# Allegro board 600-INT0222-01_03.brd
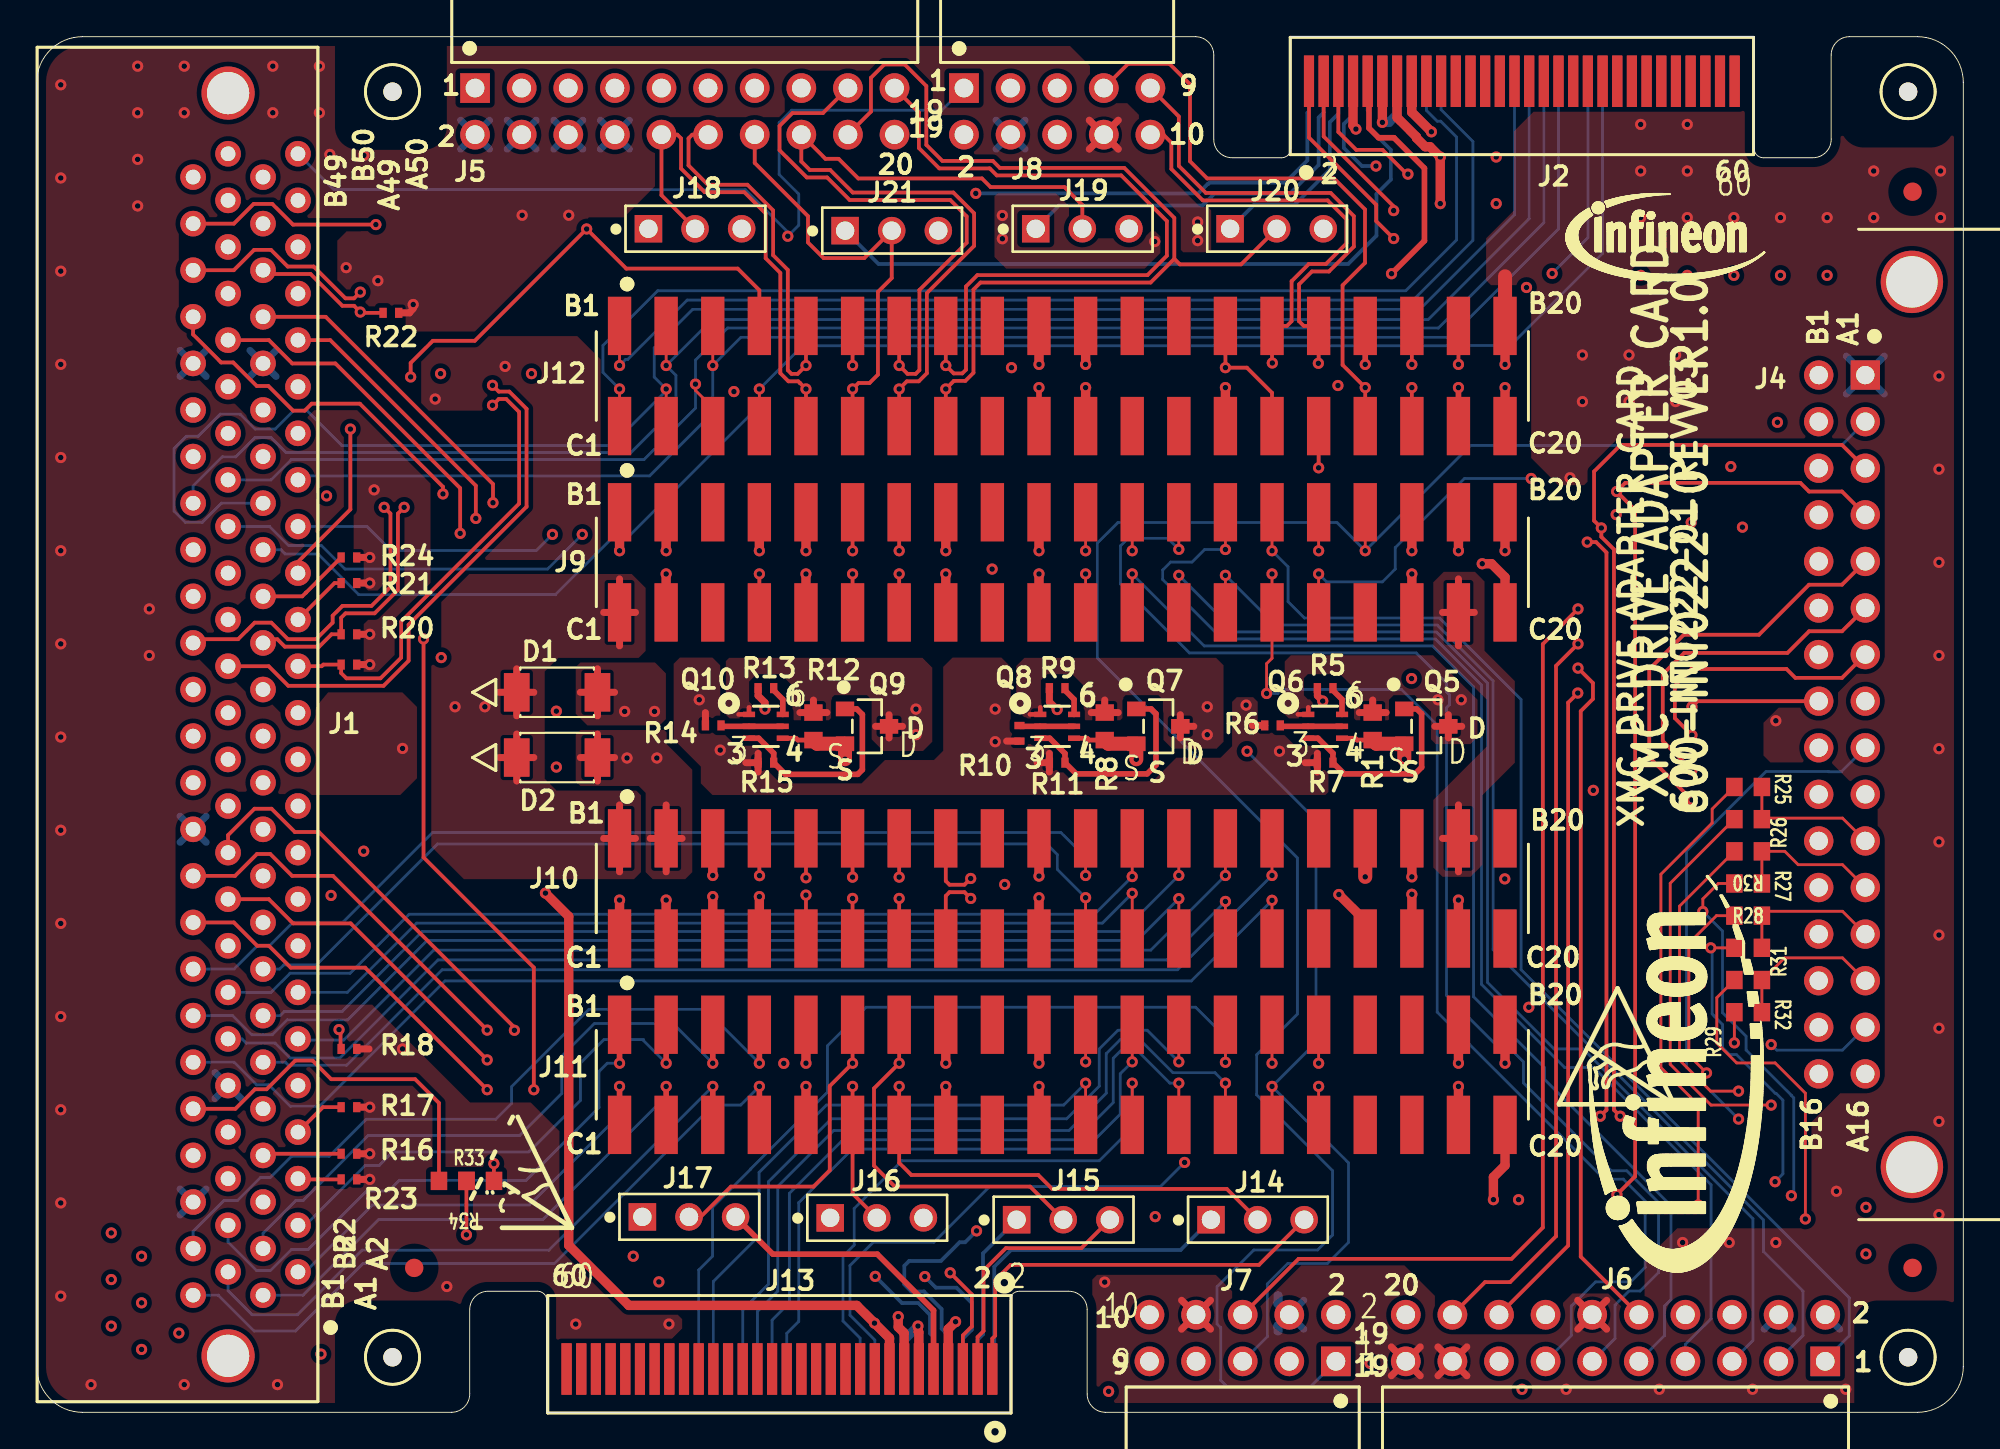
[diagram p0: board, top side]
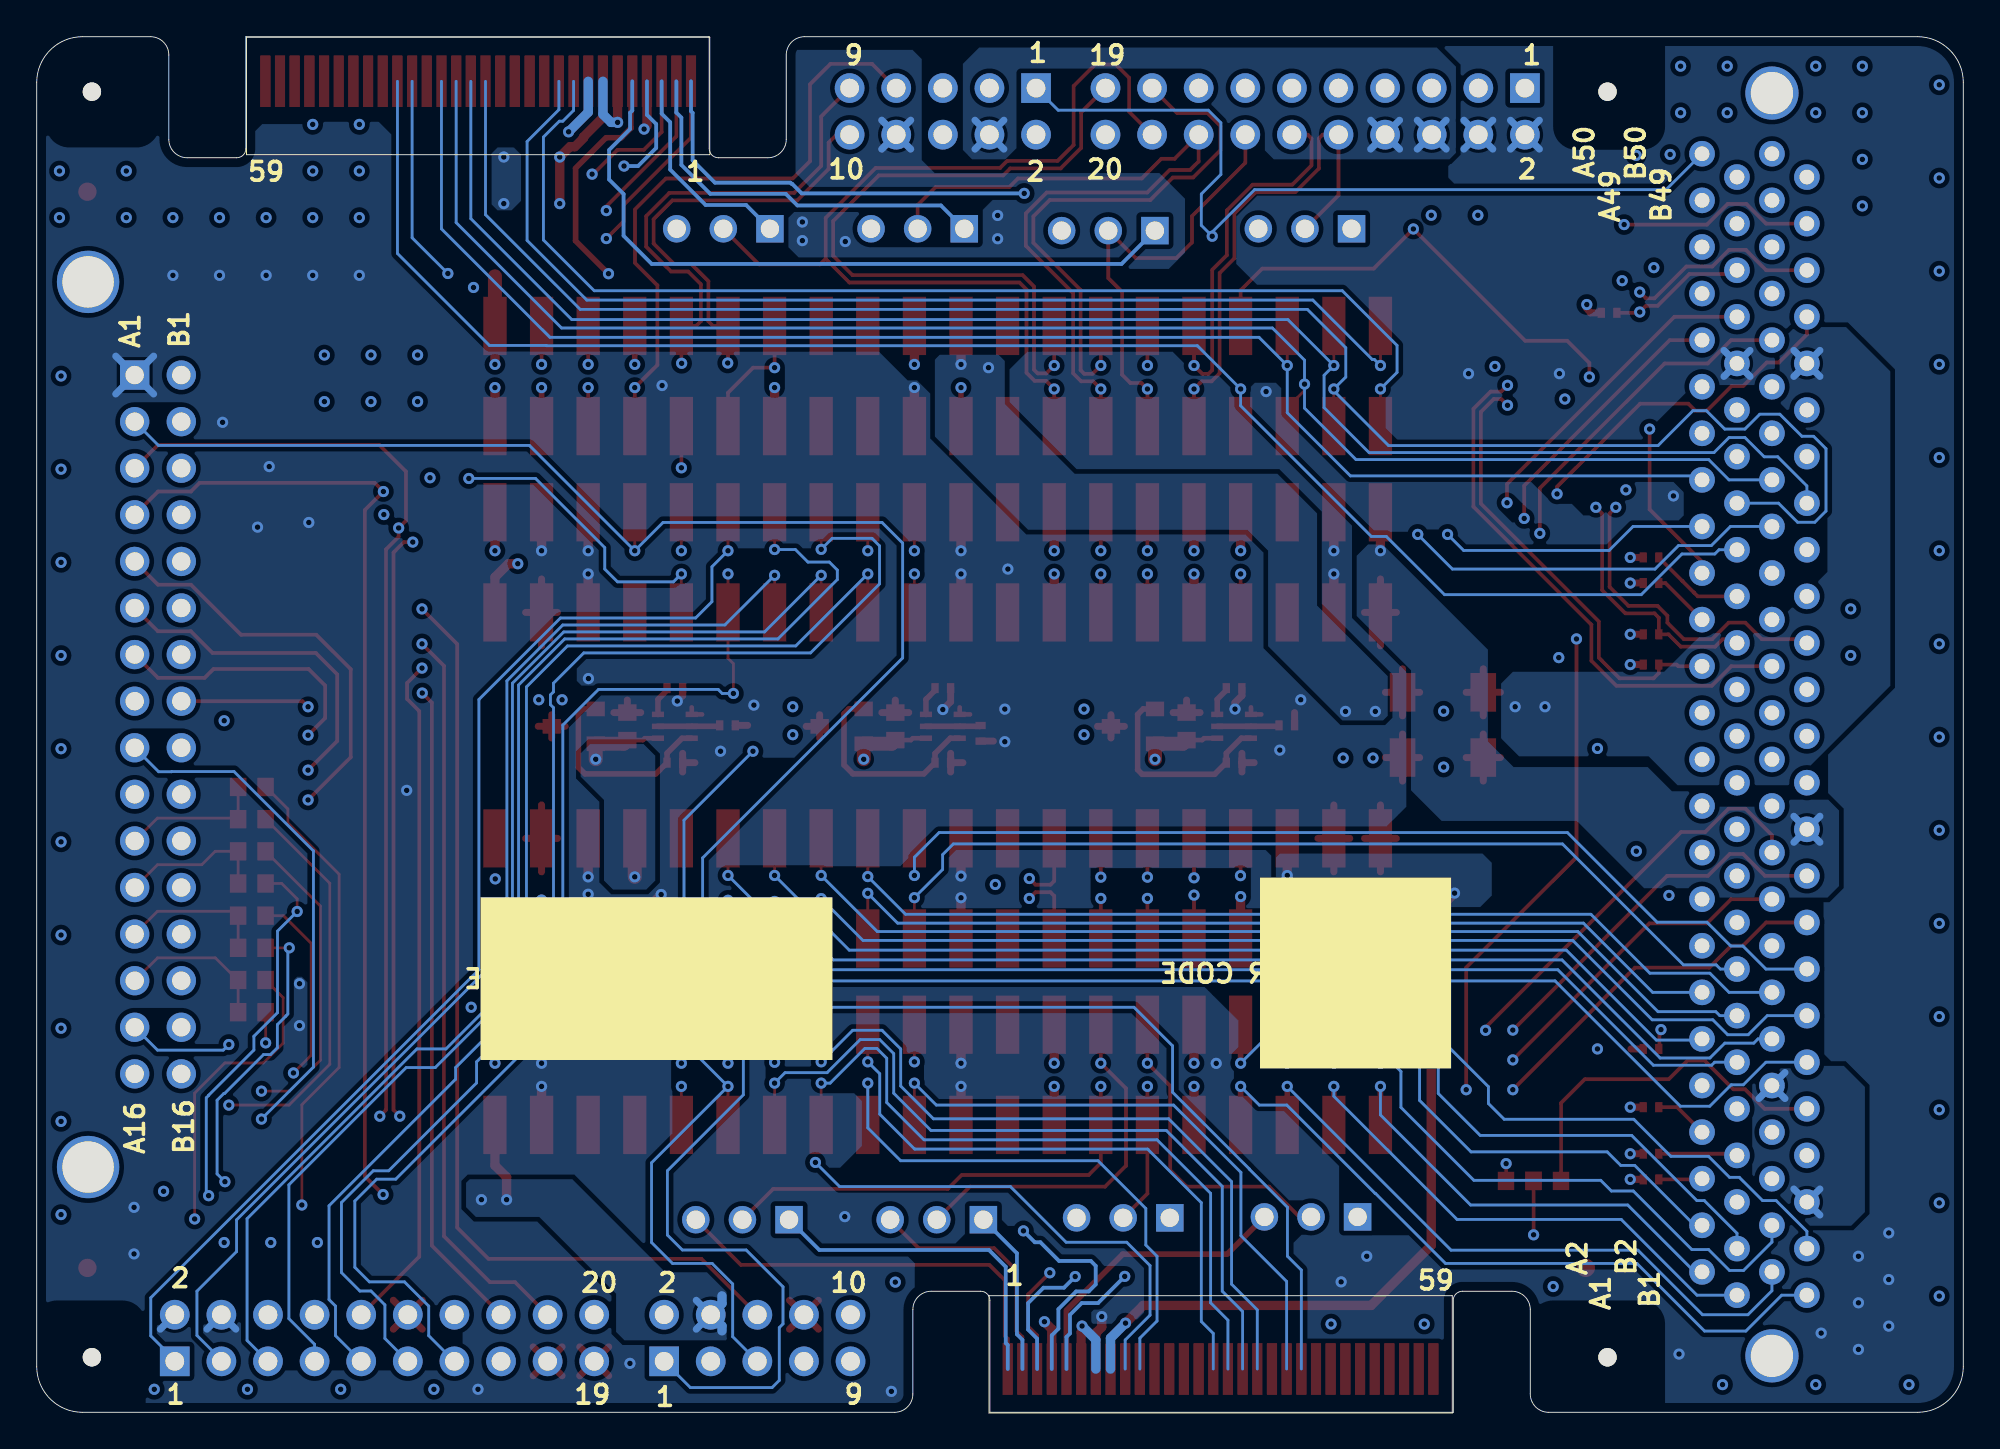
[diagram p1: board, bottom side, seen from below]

Outline 105 x 75 mm; copper layers: TOP, L02_AGND, L03_SIG1, LO4_SIG2, L05_DGND, BOTTOM. Coordinates in mm from the lower left corner of the outline.
Outline path: 0,72.5 0,2.5 arc(0.73,0.73) 2.5,0 22.6,0 arc(23.31,0.29) 23.6,1 23.6,5.6 arc(23.89,6.31) 24.6,6.6 27.3,6.6 arc(27.65,6.45) 27.8,6.1 27.8,0 53.05,0 53.05,6.1 arc(53.2,6.45) 53.55,6.6 56.25,6.6 arc(56.96,6.31) 57.25,5.6 57.25,1 arc(57.54,0.29) 58.25,0 102.5,0 arc(104.27,0.73) 105,2.5 105,72.5 arc(104.27,74.27) 102.5,75 98.8,75 arc(98.09,74.71) 97.8,74 97.8,69.4 arc(97.51,68.69) 96.8,68.4 94.1,68.4 arc(93.75,68.55) 93.6,68.9 93.6,75 68.35,75 68.35,68.9 arc(68.2,68.55) 67.85,68.4 65.15,68.4 arc(64.44,68.69) 64.15,69.4 64.15,74 arc(63.86,74.71) 63.15,75 2.5,75 arc(0.73,74.27) 0,72.5

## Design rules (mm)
constraint set DEFAULT: min track width 0.305
net group DP8_2: nets P8_2_VBEMF_U/IU(3)/PFC_I_PHASE_IN_A P8_2_VBEMF_U/IU(3)/PFC_I_PHASE_IN_A_N
net group DP9_1: nets P9_1_PFC_V_PHASE_IN_A P9_1_PFC_V_PHASE_IN_A_N
net group DP10_7: nets P10_7_VBEMF_V/IV(3)/PFC_I_PHASE_IN_B P10_7_VBEMF_V/IV(3)/PFC_I_PHASE_IN_B_N
net group DP11_0: nets P11_0_VBEMF_U/IU(1) P11_0_VBEMF_U/IU(1)_N
net group DP11_1: nets P11_1_VBEMF_V/IV(1) P11_1_VBEMF_V/IV(1)_N
net group DP11_2: nets P11_2_VBEMF_W/IW(1) P11_2_VBEMF_W/IW(1)_N
net group DP17_5: nets P17_5_VBEMF_W/IW(3)/PFC_I_PHASE_IN_C P17_5_VBEMF_W/IW(3)/PFC_I_PHASE_IN_C_N
net group DP17_6: nets P17_6_IAVG_IDCLINK(3) P17_6_IAVG_IDCLINK(3)_N
net group ANALOG_SIGNALS: nets P8_1_VBEMF_U/IU(2) P8_1_VBEMF_U/IU(2)_L P8_1_VBEMF_U/IU(2)_R P8_2_VBEMF_U/IU(3)/PFC_I_PHASE_IN_A_L P8_2_VBEMF_U/IU(3)/PFC_I_PHASE_IN_A_R P8_3_IAVG_IDCLINK(2)_L P8_4_VDCLINK1 P9_0_VBEMF_U/IU(4) P10_4_VBEMF_V/IV(4) P10_6_VBEMF_V/IV(2) P10_6_VBEMF_V/IV(2)_L P10_6_VBEMF_V/IV(2)_R P10_7_VBEMF_V/IV(3)/PFC_I_PHASE_IN_B_L P10_7_VBEMF_V/IV(3)/PFC_I_PHASE_IN_B_R P12_0_PFC_V_PHASE_IN_B P12_5_PFC_OVERCURRENT_PROT P12_6_PFC_NTC P16_3_ADC_BOARDIDENT/EXTRA_ADC4 P17_0_PFC_V_PHASE_IN_C P17_3_VBEMF_W/IW(4) P17_4_VBEMF_W/IW(2) P17_4_VBEMF_W/IW(2)_L P17_4_VBEMF_W/IW(2)_R P17_5_VBEMF_W/IW(3)/PFC_I_PHASE_IN_C_L P17_5_VBEMF_W/IW(3)/PFC_I_PHASE_IN_C_R P17_6_IAVG_IDCLINK(3)_L P17_7_IDCLINK(4) P19_0_PFC_V_DC_OUT_1 P19_1_PFC_V_DC_OUT_2 P20_0_EXTRA _ADC1/DC_LINK2 P20_1_EXTRA_ADC2/DC_LINK3 P20_2_EXTRA_ADC3
net group DIGITAL_SIGNALS: nets P1_2_CTRAP_1 P1_3_CTRAP_2 P2_4_CTRAP_3 P4_4_ENPOW1 P8_0_ENPOW2 P9_2_BRAKEGATE1 P9_3_BRAKETEMP1 P10_0_PFC_KIL_EXTRA1 P10_1_EXTRA2 P10_2_EXTRA3 P10_3_EXTRA4 P18_0_PFC_RELAY1 P18_1_PFC_RELAY2 P18_2_ENPOW3 P18_3_ENPOW4 P18_6_PWM_SYNCHRO_RECT_HIGH P18_7_PWM_SYNCHRO_RECT_LOW P23_3_CTRAP4
net group DP10_5: nets P10_5_IAVG/IDCLINK(1)_N
net group M5CONN_J4_A8PIN: nets M5CONN_J4_A8PIN P8_3_IAVG_IDCLINK(2) P10_5_IAVG/IDCLINK(1)
net group P3_0_SCB6_MISO: nets P3_0_SCB6_MISO P7_2_V2_H P7_2_V2_H/MISO
net group P3_1_SCB6_MOSI: nets P3_1_SCB6_MOSI P7_3_V2_L P7_3_V2_L/MOSI
net group P3_2_SCB6_CLK: nets P3_2_SCB6_CLK P7_4_W2_H P7_4_W2_H/CLK
net group P3_3_SCB6_SEL0: nets P3_3_SCB6_SEL0 P7_5_W2_L P7_5_W2_L/SEL0
net group SPI_HS: nets P2_1_SCB7_SDA P2_2_SCB7_SCL P3_4_SCB6_SEL1 P3_5_SCB6_SEL2

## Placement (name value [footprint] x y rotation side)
D1  PMEG3030EP,115  [DIO_NXP_SOD-128]  28.36 39.25 0 top
D2  PMEG3030EP,115  [DIO_NXP_SOD-128]  28.36 35.7 0 top
J1  FX2-100P-1.27DS(71)  [HIROSE_FX2-100P-1P27DS-71]  14.24 7.66 270 top
J2  HSEC8-130-01-L-RA_Edge_finger  [SAMTEC_HSEC8_130_EDGE]  80.94 71.77 0 top
J4  9221322921  [HARTING_9221322921]  99.66 56.55 90 top
J5  PH2RA-20-UA  [ADAMTECH_PH2RA-20-UA_CUST]  46.75 72.2 180 top
J6  PH2RA-20-UA  [ADAMTECH_PH2RA-20-UA_CUST]  74.62 2.78 0 top
J7  PH2RA-10-UA  [ADAMTECH_PH2RA-10-UA_CUST]  60.65 2.78 0 top
J8  PH2RA-10-UA  [ADAMTECH_PH2RA-10-UA_CUST]  60.7 72.2 180 top
J9  95157-440LF  [AMPHENOL_95157-440LF]  55.9 46.34 0 top
J10  95157-440LF  [AMPHENOL_95157-440LF]  55.9 28.56 0 top
J11  95157-440LF  [AMPHENOL_95157-440LF]  55.9 18.4 0 top
J12  95157-440LF  [AMPHENOL_95157-440LF]  55.9 56.5 0 top
J13  HSEC8-130-01-L-RA_Edge_finger  [SAMTEC_HSEC8_130_EDGE]  40.48 3.16 180 top
J14  HDR 3  [CTST254P1X03_W260]  64 10.5 0 top
J15  HDR 3  [CTST254P1X03_W260]  53.41 10.5 0 top
J16  HDR 3  [CTST254P1X03_W260]  43.25 10.6 0 top
J17  HDR 3  [CTST254P1X03_W260]  33.01 10.65 0 top
J18  HDR 3  [CTST254P1X03_W260]  33.34 64.53 0 top
J19  HDR 3  [CTST254P1X03_W260]  54.45 64.53 0 top
J20  HDR 3  [CTST254P1X03_W260]  65.04 64.53 0 top
J21  HDR 3  [CTST254P1X03_W260]  44.06 64.43 0 top
NOREF  -  []  50.54 69.66 0 top
NOREF#2  -  [unnamed#2]  101.99 3 0 top
NOREF#3  -  []  30.5 30.98 0 top
NOREF#4  -  []  34.31 21.13 0 top
NOREF#5  -  []  48.02 70.1 0 top
NOREF#6  -  []  68.31 74.97 0 top
NOREF#7  -  []  81.3 54.09 90 top
NOREF#8  -  [unnamed#2]  20.57 7.87 0 top
NOREF#9  -  []  30.5 58.92 0 top
NOREF#10  -  []  98.75 -1.12 90 top
NOREF#11  -  []  23.6 1 0 top
NOREF#12  -  []  73.35 -7.12 90 top
NOREF#13  -  []  68.35 74.45 0 top
NOREF#14  -  []  14.24 12.74 90 top
NOREF#15  -  []  0.02 0.58 0 top
NOREF#16  -  []  12.33 67.35 90 top
NOREF#17  -  []  27.65 6.46 0 top
NOREF#18  -  []  124.05 26.95 0 top
NOREF#19  -  []  81.3 15.99 90 top
NOREF#20  -  []  61.97 70.1 90 top
NOREF#21  -  []  34.31 49.07 0 top
NOREF#22  -  []  0 71.71 0 top
NOREF#23  -  []  23.89 69.66 90 top
NOREF#24  -  [unnamed#2]  19.39 3 0 top
NOREF#25  -  []  36.59 69.66 0 top
NOREF#26  -  []  53.05 0 0 top
NOREF#27  -  []  12.33 8.93 0 top
NOREF#28  -  []  27.85 -0.04 0 top
NOREF#29  -  []  57.25 1 0 top
NOREF#30  -  []  0 2.5 0 top
NOREF#31  -  []  186.99 280.67 0 top
NOREF#32  -  []  48.02 71.1 90 top
NOREF#33  -  []  0 2.5 0 top
NOREF#34  -  []  27.8 0 0 top
NOREF#35  -  []  34.31 59.23 0 top
NOREF#36  -  []  10.43 3.08 90 top
NOREF#37  -  []  59.38 -1.12 90 top
NOREF#38  -  []  34.31 31.29 0 top
NOREF#39  -  []  102.2 13.37 90 top
NOREF#40  -  []  127 44.55 0 top
NOREF#41  -  []  12.33 67.35 90 top
NOREF#42  -  []  13.79 -44.65 0 top
NOREF#43  -  []  24.03 6.42 0 top
NOREF#44  -  []  59.38 -7.12 90 top
NOREF#45  -  []  61.97 70.1 0 top
NOREF#46  -  []  81.3 26.15 90 top
NOREF#47  -  []  99.3 64.5 90 top
NOREF#48  -  []  93.6 74.08 0 top
NOREF#49  -  []  0.64 74.17 0 top
NOREF#50  -  []  8.52 67.35 90 top
NOREF#51  -  []  8.52 6.39 0 top
NOREF#52  -  []  73.35 -1.12 90 top
NOREF#53  -  []  93.6 73.33 0 top
NOREF#54  -  []  97.12 38.77 90 top
NOREF#55  -  []  15.32 0.58 90 top
NOREF#56  -  []  4.52 0 90 top
NOREF#57  -  []  27.85 -0.04 90 top
NOREF#58  -  []  93.56 68.57 90 top
NOREF#59  -  []  128.95 69.84 0 top
NOREF#60  -  []  59.38 -7.12 0 top
NOREF#61  -  []  30.5 20.82 0 top
NOREF#62  -  []  31.77 53.77 90 top
NOREF#63  -  []  31.77 43.61 90 top
NOREF#64  -  []  102.2 13.37 90 top
NOREF#65  -  []  68.27 5.32 0 top
NOREF#66  -  []  34.05 72.2 90 top
NOREF#67  -  []  31.77 15.67 90 top
NOREF#68  -  []  64.15 73.41 0 top
NOREF#69  -  []  60.65 2.78 90 top
NOREF#70  -  []  61.97 71.1 90 top
NOREF#71  -  [unnamed#2]  101.99 72 0 top
NOREF#72  -  [unnamed#2]  102.23 66.55 0 top
NOREF#73  -  [unnamed#2]  102.23 7.87 0 top
NOREF#74  -  []  50.54 69.66 90 top
NOREF#75  -  []  81.3 43.93 90 top
NOREF#76  -  []  31.77 25.83 90 top
NOREF#77  -  []  73.35 -7.12 0 top
NOREF#78  -  [unnamed#2]  19.39 72 0 top
NOREF#79  -  []  45.3 10.5 0 top
NOREF#80  -  []  30.5 48.76 0 top
NOREF#81  -  []  82.24 5.32 0 top
NOREF#82  -  []  74.62 2.78 90 top
NOREF#83  -  []  48.02 70.1 90 top
Q5  IRLML2244TRPbF  [SOT95P300X115-3N]  75.73 37.4 0 top
Q6  BCM857BS,115  [SOT65P210X110-6N]  70.22 37.4 0 top
Q7  IRLML2244TRPbF  [SOT95P300X115-3N]  61.13 37.4 0 top
Q8  BCM857BS,115  [SOT65P210X110-6N]  55.62 37.4 0 top
Q9  IRLML2244TRPbF  [SOT95P300X115-3N]  45.25 37.4 0 top
Q10  BCM857BS,115  [SOT65P210X110-6N]  39.74 37.4 0 top
R1  0 OHM  [RESC1608_0603N]  72.81 37.4 270 top
R5  10K  [RESC1005_0402N]  70.22 39.48 180 top
R6  100K  [RESC1005_0402N]  67.35 37.45 0 top
R7  10K  [RESC1005_0402N]  70.22 35.42 180 top
R8  0 OHM  [RESC1608_0603N]  58.21 37.4 270 top
R9  10K  [RESC1005_0402N]  55.62 39.48 180 top
R10  100K  [RESC1005_0402N]  53.56 37.02 90 top
R11  10K  [RESC1005_0402N]  55.62 35.42 180 top
R12  0 OHM  [RESC1608_0603N]  42.33 37.4 270 top
R13  10K  [RESC1005_0402N]  39.74 39.48 180 top
R14  100K  [RESC1005_0402N]  36.87 37.45 0 top
R15  10K  [RESC1005_0402N]  39.74 35.42 180 top
R16  0 OHM  [RESC1005_0402N]  17.02 14.1 0 top
R17  0 OHM  [RESC1005_0402N]  17.02 16.64 0 top
R18  0 OHM  [RESC1005_0402N]  17.02 19.81 0 top
R19  0 OHM  [RESC1005_0402N]  17.02 40.77 0 top
R20  0 OHM  [RESC1005_0402N]  17.02 42.42 0 top
R21  0 OHM  [RESC1005_0402N]  17.02 45.21 0 top
R22  0 OHM  [RESC1005_0402N]  19.3 59.94 0 top
R23  0 OHM  [RESC1005_0402N]  17.02 12.7 0 top
R24  0 OHM  [RESC1005_0402N]  17.02 46.61 0 top
R25  0 OHM  [RESC1608_0603N]  93.27 34.09 0 top
R26  0 OHM  [RESC1608_0603N]  93.27 32.34 0 top
R27  0 OHM  [RESC1608_0603N]  93.27 30.59 0 top
R28  0 OHM  [RESC1608_0603N]  93.27 27.08 0 top
R29  0 OHM  [RESC1608_0603N]  93.27 21.82 0 top
R30  0 OHM  [RESC1608_0603N]  93.27 28.83 0 top
R31  0 OHM  [RESC1608_0603N]  93.27 25.32 0 top
R32  0 OHM  [RESC1608_0603N]  93.27 23.57 0 top
R33  0 OHM  [RESC1608_0603N]  22.67 12.62 0 top
R34  0 OHM  [RESC1608_0603N]  24.17 12.62 180 top

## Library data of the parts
D1 D2 = DIO-SCHOTTKY: User Part Number: Part No
J1 = FX2100P127DS71
J2 J13 = EDGE_CARD_HSEC8
J4 = PLG_2x16_SHRD
J5 J6 = PLG-20-ODD-EVEN-J
J7 J8 = PLG-10-ODD-EVEN-J
J9-J12 = 95157-440LF_PLG-40-C-B
J14-J21 = PLG-3-J
Q5 Q7 Q9 = IRLML2244TRPbF
Q6 Q8 Q10 = PNP-PNP-BCM857BS
R1 R5-R34 = RES

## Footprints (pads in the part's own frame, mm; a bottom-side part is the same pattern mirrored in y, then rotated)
ADAMTECH_PH2RA-10-UA_CUST
  rect 1.62x1.62 hole 1.02: 1(10.16,0)
  round 1.62 hole 1.02: 2(10.16,2.54) 3(7.62,0) 4(7.62,2.54) 5(5.08,0) 6(5.08,2.54) 7(2.54,0) 8(2.54,2.54) 9(0,0) 10(0,2.54)
ADAMTECH_PH2RA-20-UA_CUST
  rect 1.62x1.62 hole 1.02: 1(22.86,0)
  round 1.62 hole 1.02: 2(22.86,2.54) 3(20.32,0) 4(20.32,2.54) 5(17.78,0) 6(17.78,2.54) 7(15.24,0) 8(15.24,2.54) 9(12.7,0) 10(12.7,2.54) 11(10.16,0) 12(10.16,2.54) 13(7.62,0) 14(7.62,2.54) 15(5.08,0) 16(5.08,2.54) 17(2.54,0) 18(2.54,2.54) 19(0,0) 20(0,2.54)
AMPHENOL_95157-440LF
  rect 1.27x3.18 smd: B1(-24.13,2.73) B2(-21.59,2.73) B3(-19.05,2.73) B4(-16.51,2.73) B5(-13.97,2.73) B6(-11.43,2.73) B7(-8.89,2.73) B8(-6.35,2.73) B9(-3.81,2.73) B10(-1.27,2.73) B11(1.27,2.73) B12(3.81,2.73) B13(6.35,2.73) B14(8.89,2.73) B15(11.43,2.73) B16(13.97,2.73) B17(16.51,2.73) B18(19.05,2.73) B19(21.59,2.73) B20(24.13,2.73) C1(-24.13,-2.73) C2(-21.59,-2.73) C3(-19.05,-2.73) C4(-16.51,-2.73) C5(-13.97,-2.73) C6(-11.43,-2.73) C7(-8.89,-2.73) C8(-6.35,-2.73) C9(-3.81,-2.73) C10(-1.27,-2.73) C11(1.27,-2.73) C12(3.81,-2.73) C13(6.35,-2.73) C14(8.89,-2.73) C15(11.43,-2.73) C16(13.97,-2.73) C17(16.51,-2.73) C18(19.05,-2.73) C19(21.59,-2.73) C20(24.13,-2.73)
CTST254P1X03_W260
  rect 1.5x1.5 hole 1: 1(0,0)
  round 1.5 hole 1: 2(2.54,0) 3(5.08,0)
DIO_NXP_SOD-128
  rect 1.4x2.1 smd: A(2.2,0) K(-2.2,0)
HARTING_9221322921
  rect 1.6x1.6 hole 1: A1(0,0)
  round 1.6 hole 1: A2(-2.54,0) A3(-5.08,0) A4(-7.62,0) A5(-10.16,0) A6(-12.7,0) A7(-15.24,0) A8(-17.78,0) A9(-20.32,0) A10(-22.86,0) A11(-25.4,0) A12(-27.94,0) A13(-30.48,0) A14(-33.02,0) A15(-35.56,0) A16(-38.1,0) B1(0,2.54) B2(-2.54,2.54) B3(-5.08,2.54) B4(-7.62,2.54) B5(-10.16,2.54) B6(-12.7,2.54) B7(-15.24,2.54) B8(-17.78,2.54) B9(-20.32,2.54) B10(-22.86,2.54) B11(-25.4,2.54) B12(-27.94,2.54) B13(-30.48,2.54) B14(-33.02,2.54) B15(-35.56,2.54) B16(-38.1,2.54)
  round 3.4 hole 2.8: SH1(5.08,-2.54) SH2(-43.18,-2.54)
HIROSE_FX2-100P-1P27DS-71
  round 1.4 hole 0.8: A1(1.27,-1.905) A2(0,0) A3(-1.27,-1.905) A4(-2.54,0) A5(-3.81,-1.905) A6(-5.08,0) A7(-6.35,-1.905) A8(-7.62,0) A9(-8.89,-1.905) A10(-10.16,0) A11(-11.43,-1.905) A12(-12.7,0) A13(-13.97,-1.905) A14(-15.24,0) A15(-16.51,-1.905) A16(-17.78,0) A17(-19.05,-1.905) A18(-20.32,0) A19(-21.59,-1.905) A20(-22.86,0) A21(-24.13,-1.905) A22(-25.4,0) A23(-26.67,-1.905) A24(-27.94,0) A25(-29.21,-1.905) A26(-30.48,0) A27(-31.75,-1.905) A28(-33.02,0) A29(-34.29,-1.905) A30(-35.56,0) A31(-36.83,-1.905) A32(-38.1,0) A33(-39.37,-1.905) A34(-40.64,0) A35(-41.91,-1.905) A36(-43.18,0) A37(-44.45,-1.905) A38(-45.72,0) A39(-46.99,-1.905) A40(-48.26,0) A41(-49.53,-1.905) A42(-50.8,0) A43(-52.07,-1.905) A44(-53.34,0) A45(-54.61,-1.905) A46(-55.88,0) A47(-57.15,-1.905) A48(-58.42,0) A49(-59.69,-1.905) A50(-60.96,0) B1(1.27,-5.715) B2(0,-3.81) B3(-1.27,-5.715) B4(-2.54,-3.81) B5(-3.81,-5.715) B6(-5.08,-3.81) B7(-6.35,-5.715) B8(-7.62,-3.81) B9(-8.89,-5.715) B10(-10.16,-3.81) B11(-11.43,-5.715) B12(-12.7,-3.81) B13(-13.97,-5.715) B14(-15.24,-3.81) B15(-16.51,-5.715) B16(-17.78,-3.81) B17(-19.05,-5.715) B18(-20.32,-3.81) B19(-21.59,-5.715) B20(-22.86,-3.81) B21(-24.13,-5.715) B22(-25.4,-3.81) B23(-26.67,-5.715) B24(-27.94,-3.81) B25(-29.21,-5.715) B26(-30.48,-3.81) B27(-31.75,-5.715) B28(-33.02,-3.81) B29(-34.29,-5.715) B30(-35.56,-3.81) B31(-36.83,-5.715) B32(-38.1,-3.81) B33(-39.37,-5.715) B34(-40.64,-3.81) B35(-41.91,-5.715) B36(-43.18,-3.81) B37(-44.45,-5.715) B38(-45.72,-3.81) B39(-46.99,-5.715) B40(-48.26,-3.81) B41(-49.53,-5.715) B42(-50.8,-3.81) B43(-52.07,-5.715) B44(-53.34,-3.81) B45(-54.61,-5.715) B46(-55.88,-3.81) B47(-57.15,-5.715) B48(-58.42,-3.81) B49(-59.69,-5.715) B50(-60.96,-3.81)
  round 2.9 hole 2.3: SH1(4.58,-3.81) SH2(-64.27,-3.81)
RESC1005_0402N
  rect 0.4x0.55 smd: 1(-0.425,0) 2(0.425,0)
RESC1608_0603N
  rect 0.9x1 smd: 1(-0.75,0) 2(0.75,0)
SAMTEC_HSEC8_130_EDGE
  rect 0.55x2.8 smd: 1(-11.6,0.8) 2(-11.6,0.8) 3(-10.8,0.8) 4(-10.8,0.8) 5(-10,0.8) 6(-10,0.8) 7(-9.2,0.8) 8(-9.2,0.8) 9(-8.4,0.8) 10(-8.4,0.8) 11(-7.6,0.8) 12(-7.6,0.8) 13(-6.8,0.8) 14(-6.8,0.8) 15(-6,0.8) 16(-6,0.8) 17(-5.2,0.8) 18(-5.2,0.8) 19(-4.4,0.8) 20(-4.4,0.8) 21(-3.6,0.8) 22(-3.6,0.8) 23(-2.8,0.8) 24(-2.8,0.8) 25(-2,0.8) 26(-2,0.8) 27(-1.2,0.8) 28(-1.2,0.8) 29(-0.4,0.8) 30(-0.4,0.8) 31(0.4,0.8) 32(0.4,0.8) 33(1.2,0.8) 34(1.2,0.8) 35(2,0.8) 36(2,0.8) 37(2.8,0.8) 38(2.8,0.8) 39(3.6,0.8) 40(3.6,0.8) 41(4.4,0.8) 42(4.4,0.8) 43(5.2,0.8) 44(5.2,0.8) 45(6,0.8) 46(6,0.8) 47(6.8,0.8) 48(6.8,0.8) 49(7.6,0.8) 50(7.6,0.8) 51(8.4,0.8) 52(8.4,0.8) 53(9.2,0.8) 54(9.2,0.8) 55(10,0.8) 56(10,0.8) 57(10.8,0.8) 58(10.8,0.8) 59(11.6,0.8) 60(11.6,0.8)
SOT65P210X110-6N
  rect 0.66x0.3 smd: 1(-0.92,0.65) 2(-0.92,0) 3(-0.92,-0.65) 4(0.92,-0.65) 5(0.92,0) 6(0.92,0.65)
SOT95P300X115-3N
  rect 1x0.8 smd: D(1.2,0) G(-1.2,0.95) S(-1.2,-0.95)
unnamed#2
  round 1 hole 2.5 unplated: (0,0)

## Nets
3.3V_PWR_OUT_SYS: J1.B21 J9.B1
AGND: J1.A16 J1.A17 J1.A18 J1.A19 J1.A20 J2.8 J2.12 J2.13 J6.12 J6.17 J6.19 J7.8 J8.8 J9.B4 J9.B5 J9.B8 J9.C5 J9.C8 J10.C4 J11.B5 J11.B8 J11.C5 J11.C8 J12.B20 J12.C14 J12.C20 J13.8 J13.12 J13.13 R16.2 R17.2 R18.2 R19.2 R20.2 R21.2 R22.2 R23.2 R24.2
GND: J1.A5 J1.A10 J1.A21 J1.A41 J2.14 J4.A1 J5.2 J5.4 J6.2 J6.4 J7.2 J8.2 J9.B2 J9.B10 J9.B18 J9.B19 J9.C2 J9.C10 J9.C18 J10.B10 J10.B18 J10.C1 J10.C2 J10.C3 J10.C10 J10.C17 J10.C18 J10.C19 J11.B10 J11.B19 J11.B20 J11.C10 J11.C19 J12.C10 J12.C11 J13.14 R5.2 R6.1 R7.2 R9.2 R10.1 R11.2 R13.2 R14.1 R15.2
VCC1_3.3V: J5.6 J5.8 J8.4 J12.B11
VCC1_5V: J4.B1 J9.B20 Q5.D Q6.1 R1.1
VCC1_15V: D1.A J5.20 J12.B10
VCC2_3.3V: J6.6 J6.8 J7.4 J11.C20
VCC2_5V: J2.15 J2.16 J9.C20 Q7.D Q8.1 R8.1
VCC2_15V: D2.A J6.20 J10.B2
VCC3_5V: J10.B3 J13.15 J13.16 Q9.D Q10.1 R12.1
M5CONN_J4_A8PIN: J4.A8 R34.1
P1_2_CTRAP_1: J1.A14 J4.B15 J10.C12
P1_3_CTRAP_2: J1.A25 J4.A15 J11.B14 J13.41
P2_1_SCB7_SDA: J1.B1 J11.C4
P2_2_SCB7_SCL: J1.A1 J11.C2
P2_4_CTRAP_3: J1.A33 J2.41 J5.13 J12.C4
P3_0_SCB6_MISO: J1.A3 J11.B3 R30.1
P3_1_SCB6_MOSI: J1.B2 J11.C3 R25.1
P3_2_SCB6_CLK: J1.A2 J11.C1 R32.1
P3_3_SCB6_SEL0: J1.B3 J11.B4 R31.1
P3_4_SCB6_SEL1: J1.A4 J11.B2
P3_5_SCB6_SEL2: J1.B4 J11.B1
P4_4_ENPOW1: J1.B14 J4.B16 J10.B12
P5_0_U4_H: J1.B38 J6.1 J9.B15
P5_1_U4_L: J1.A38 J6.3 J9.C14
P6_0_U1_H: J1.B11 J4.B10 J10.C15
P6_1_U1_L: J1.A11 J4.B9 J10.B15
P6_2_V1_H: J1.B12 J4.B12 J10.C14
P6_3_V1_L: J1.A12 J4.B11 J10.B14
P6_4_W1_H: J1.B13 J4.B14 J10.C13
P6_5_W1_L: J1.A13 J4.B13 J10.B13
P7_0_U2_H: J1.B22 J4.A10 J11.B11 J13.17
P7_1_U2_L: J1.A22 J4.A9 J11.C12 J13.19
P7_2_V2_H: J1.B23 J11.C13 J13.31 R27.1
P7_2_V2_H/MISO: J4.A12 R27.2 R30.2
P7_3_V2_L: J1.A23 J11.B12 J13.29 R26.1
P7_3_V2_L/MOSI: J4.A11 R25.2 R26.2
P7_4_W2_H: J1.B24 J11.C14 J13.33 R29.1
P7_4_W2_H/CLK: J4.A14 R29.2 R32.2
P7_5_W2_L: J1.A24 J11.B13 J13.35 R28.1
P7_5_W2_L/SEL0: J4.A13 R28.2 R31.2
P8_0_ENPOW2: J1.B25 J4.A16 J11.C11 J13.39
P8_1_VBEMF_U/IU(2): J1.B17 J4.B5 J11.C7 J14.2
P8_1_VBEMF_U/IU(2)_L: J13.1 J14.1
P8_1_VBEMF_U/IU(2)_R: J13.2 J14.3
P8_2_VBEMF_U/IU(3)/PFC_I_PHASE_IN_A: J1.B28 J5.10 J12.C5 J18.2
P8_2_VBEMF_U/IU(3)/PFC_I_PHASE_IN_A_L: J2.1 J18.1
P8_2_VBEMF_U/IU(3)/PFC_I_PHASE_IN_A_N: J1.A28 J5.12 J12.B5 R19.1
P8_2_VBEMF_U/IU(3)/PFC_I_PHASE_IN_A_R: J2.2 J18.3
P8_3_IAVG_IDCLINK(2): J1.B20 J11.B6 J17.2 R33.2 R34.2
P8_3_IAVG_IDCLINK(2)_L: J13.9 J17.1
P8_4_VDCLINK1: J1.B16 J4.B4 J10.B4
P9_0_VBEMF_U/IU(4): J1.A42 J6.10 J9.B6
P9_1_PFC_V_PHASE_IN_A: J1.B45 J4.A3 J7.9 J8.9 J12.B16
P9_1_PFC_V_PHASE_IN_A_N: J1.A45 J7.10 J8.10 J12.B15 R22.1
P9_2_BRAKEGATE1: J1.A15 J4.B2 J10.C11
P9_3_BRAKETEMP1: J1.B15 J4.B3 J10.B11
P10_0_PFC_KIL_EXTRA1: J1.A26 J7.5 J8.5 J11.C15
P10_1_EXTRA2: J1.B26 J11.B15
P10_2_EXTRA3: J1.A27 J11.C16
P10_3_EXTRA4: J1.B27 J11.B16
P10_4_VBEMF_V/IV(4): J1.B42 J6.16 J9.C6
P10_5_IAVG/IDCLINK(1): J1.B9 J4.B8 J10.C5 R33.1
P10_5_IAVG/IDCLINK(1)_N: J1.A9 J10.B5 R18.1
P10_6_VBEMF_V/IV(2): J1.B18 J4.B6 J11.B7 J15.2
P10_6_VBEMF_V/IV(2)_L: J13.3 J15.1
P10_6_VBEMF_V/IV(2)_R: J13.4 J15.3
P10_7_VBEMF_V/IV(3)/PFC_I_PHASE_IN_B: J1.B29 J5.16 J12.C7 J19.2
P10_7_VBEMF_V/IV(3)/PFC_I_PHASE_IN_B_L: J2.3 J19.1
P10_7_VBEMF_V/IV(3)/PFC_I_PHASE_IN_B_N: J1.A29 J5.17 J12.B7 R20.1
P10_7_VBEMF_V/IV(3)/PFC_I_PHASE_IN_B_R: J2.4 J19.3
P11_0_VBEMF_U/IU(1): J1.B6 J4.A5 J10.C8
P11_0_VBEMF_U/IU(1)_N: J1.A6 J10.B8 R23.1
P11_1_VBEMF_V/IV(1): J1.B7 J4.A6 J10.C7
P11_1_VBEMF_V/IV(1)_N: J1.A7 J10.B7 R16.1
P11_2_VBEMF_W/IW(1): J1.B8 J4.A7 J10.C6
P11_2_VBEMF_W/IW(1)_N: J1.A8 J10.B6 R17.1
P12_0_PFC_V_PHASE_IN_B: J1.A46 J4.A4 J7.7 J8.7 J12.C17
P12_5_PFC_OVERCURRENT_PROT: J1.A47 J12.C19
P12_6_PFC_NTC: J1.B48 J12.B19
P13_0_U3_H/PFC_PWM_A_1: J1.B34 J2.17 J5.1 J12.C1
P13_1_U3_L/PFC_PWM_A_2: J1.A34 J2.19 J5.3 J12.B1
P13_2_V3_H/PFC_PWM_B_1: J1.B35 J2.31 J5.5 J12.B2
P13_3_V3_L/PFC_PWM_B_2: J1.A35 J2.29 J5.7 J12.C2
P13_4_W3_H/PFC_PWM_C_1: J1.B36 J2.33 J5.9 J12.C3
P13_5_W3_L/PFC_PWM_C_2: J1.A36 J2.35 J5.11 J12.B3
P14_0_V4_H: J1.B39 J6.5 J9.C13
P16_3_ADC_BOARDIDENT/EXTRA_ADC4: J1.A44 J12.B14 J12.C15
P17_0_PFC_V_PHASE_IN_C: J1.B46 J12.C18
P17_3_VBEMF_W/IW(4): J1.A43 J6.18 J9.C7
P17_4_VBEMF_W/IW(2): J1.B19 J4.B7 J11.C6 J16.2
P17_4_VBEMF_W/IW(2)_L: J13.5 J16.1
P17_4_VBEMF_W/IW(2)_R: J13.6 J16.3
P17_5_VBEMF_W/IW(3)/PFC_I_PHASE_IN_C: J1.B30 J5.18 J12.C8 J20.2
P17_5_VBEMF_W/IW(3)/PFC_I_PHASE_IN_C_L: J2.5 J20.1
P17_5_VBEMF_W/IW(3)/PFC_I_PHASE_IN_C_N: J1.A30 J5.19 J12.B8 R21.1
P17_5_VBEMF_W/IW(3)/PFC_I_PHASE_IN_C_R: J2.6 J20.3
P17_6_IAVG_IDCLINK(3): J1.B31 J5.14 J8.6 J12.C6 J21.2
P17_6_IAVG_IDCLINK(3)_L: J2.9 J21.1
P17_6_IAVG_IDCLINK(3)_N: J1.A31 J12.B6 R24.1
P17_7_IDCLINK(4): J1.B43 J6.14 J7.6 J9.B7
P18_0_PFC_RELAY1: J1.A49 J9.C11
P18_1_PFC_RELAY2: J1.B49 J9.B12
P18_2_ENPOW3: J1.B33 J2.39 J9.C16
P18_3_ENPOW4: J1.B37 J9.B16
P18_4_W4_H: J1.B40 J6.9 J9.C12
P18_5_W4_L: J1.A40 J6.11 J9.B13
P18_6_PWM_SYNCHRO_RECT_HIGH: J1.A50 J4.A2 J7.1 J8.1 J9.B17
P18_7_PWM_SYNCHRO_RECT_LOW: J1.B50 J9.B11
P19_0_PFC_V_DC_OUT_1: J1.B47 J12.B17
P19_1_PFC_V_DC_OUT_2: J1.A48 J12.B18
P20_0_EXTRA _ADC1/DC_LINK2: J1.A32 J2.7 J5.15 J12.B4
P20_1_EXTRA_ADC2/DC_LINK3: J1.B32 J6.15 J9.C4 J13.7
P20_2_EXTRA_ADC3: J1.B44 J12.C16
P23_3_CTRAP4: J1.A37 J6.13 J9.C15
P_14_1_V4_L: J1.A39 J6.7 J9.B14
PWR_IN_5V: J1.B5 J1.B10 J10.B17 Q5.S(\S\) Q6.4(\E\) Q7.S(\S\) Q8.4(\E\) Q9.S(\S\) Q10.4(\E\) R1.2 R8.2 R12.2
PWR_IN_24V*: D1.K(\K\) D2.K(\K\) J1.B41 J9.C1 J10.B1
PWR_OUT_SYS: J9.C19 J10.B19
SH1-1: J2.10 J13.10 J17.3 J21.3
N2988165: Q5.G Q6.3 R7.1
N2988205: Q7.G Q8.3 R11.1
N2988245: Q9.G Q10.3 R15.1
N2988267: Q6.2 Q6.5 R6.2
N2988279: Q8.2 Q8.5 R10.2
N2988291: Q10.2 Q10.5 R14.2
N2988319: Q6.6 R5.1
N2988327: Q8.6 R9.1
N2988335: Q10.6 R13.1

Pads without a net: J1 SH1 SH2; J2 11 18 20 21 22 23 24 25 26 27 28 30 32 34 36 37 38 40 42 43 44 45 46 47 48 49 50 51 52 53 54 55 56 57 58 59 60; J4 SH1 SH2; J7 3; J8 3; J9 B3 B9 C3 C9 C17; J10 B9 B16 B20 C9 C16 C20; J11 B9 B17 B18 C9 C17 C18; J12 B9 B12 B13 C9 C12 C13; J13 11 18 20 21 22 23 24 25 26 27 28 30 32 34 36 37 38 40 42 43 44 45 46 47 48 49 50 51 52 53 54 55 56 57 58 59 60

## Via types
v1: diameter 0.61, hole 0.305, TOP to BOTTOM, 377 vias

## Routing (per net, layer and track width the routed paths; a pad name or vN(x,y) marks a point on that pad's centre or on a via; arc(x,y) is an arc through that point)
3.3V_PWR_OUT_SYS: length 6.1
  TOP w0.508: J9.B1 v1(31.77,46.97)
  BOTTOM w0.381: J1.B21 9.23,32.5 ; J1.B21 7.81,31.08 ; J1.B21 9.23,31.08 ; J1.B21 7.81,32.5
AGND: length 159.6
  TOP w0.381: J6.12 85.56,6.11 ; J6.12 85.56,4.53 ; J6.12 83.99,4.53 ; J6.12 83.99,6.11 ; J6.19 75.4,1.99 ; J6.19 73.83,3.57 ; J6.19 75.4,3.57 ; J6.19 73.83,1.99 ; 62.4,4.53 J7.8 ; J7.8 63.97,6.11 ; J7.8 62.4,6.11 ; J7.8 63.97,4.53 ; R21.2 v1(18.15,45.21) ; R19.2 v1(18.15,40.77) ; R16.2 v1(18.15,14.1) ; R24.2 v1(18.15,46.61) ; J6.17 77.94,3.57 ; J6.17 76.37,1.99 ; J6.17 76.37,3.57 ; J6.17 77.94,1.99 ; v1(20.52,60.4) 20.52,60.18 20.32,59.94 R22.2 ; R18.2 18.11,19.81 ; J8.8 58.94,68.87 ; J8.8 57.37,68.87 ; J8.8 57.37,70.45 ; J8.8 58.94,70.45 ; R17.2 v1(18.15,16.64) ; R23.2 v1(18.15,12.7) ; R20.2 v1(18.15,42.42)
  TOP w0.508: J11.C5 v1(41.93,17.77) ; J11.B8 v1(49.55,19.03) ; J13.8 49.68,4.54 v1(50.08,4.94) ; J11.B5 v1(41.93,19.03) ; J12.B20 v1(80.03,57.13) ; J12.C20 v1(80.03,55.87) ; J9.B5 v1(41.93,46.97) ; J9.B8 v1(49.55,46.97) ; J12.C14 v1(64.79,55.87) ; v1(71.9,69.96) 71.9,69.99 71.74,70.15 J2.8 ; J2.12 v1(73.34,70.33) ; J9.B4 v1(39.39,46.97) ; J11.C8 v1(49.55,17.77) ; J9.C8 v1(49.55,45.71) ; J10.C4 v1(39.39,28.12) ; J13.12 48.08,4.36 48.05,4.39 48.05,4.68 v1(48.03,4.7) ; J9.C5 v1(41.93,45.71)
  TOP w0.762: J12.B20 80.03,61.94
  L02_AGND w0.381: 62.4,6.11 J7.8 ; J7.8 63.97,4.53 ; J7.8 62.4,4.53 ; J7.8 63.97,6.11 ; J6.17 77.94,3.57 ; J6.17 76.37,3.57 ; J6.17 76.37,1.99 ; J6.17 77.94,1.99 ; J1.A17 13.04,27.42 ; J1.A17 13.04,26 ; J1.A17 11.62,26 ; J1.A17 11.62,27.42 ; J1.A19 13.04,29.96 ; J1.A19 11.62,28.54 ; J1.A19 13.04,28.54 ; J1.A19 11.62,29.96 ; J1.A18 14.95,28.69 ; J1.A18 13.53,27.27 ; J1.A18 14.95,27.27 ; J1.A18 13.53,28.69 ; J1.A20 14.95,31.23 ; J1.A20 14.95,29.81 ; J1.A20 13.53,31.23 ; J1.A20 13.53,29.81 ; J6.19 75.4,1.99 ; J6.19 73.83,3.57 ; J6.19 75.4,3.57 ; J6.19 73.83,1.99 ; 13.53,26.15 J1.A16 ; J1.A16 13.53,24.73 ; J1.A16 14.95,24.73 ; J1.A16 14.95,26.15 ; 83.99,6.11 J6.12 ; J6.12 83.99,4.53 ; J6.12 85.56,4.53 ; J6.12 85.56,6.11 ; 57.37,68.87 J8.8 ; J8.8 58.94,70.45 ; J8.8 58.94,68.87 ; J8.8 57.37,70.45
  L03_SIG1 w0.381: 76.37,1.99 J6.17 ; J6.17 77.94,1.99 ; J6.17 77.94,3.57 ; J6.17 76.37,3.57 ; J6.19 75.4,3.57 ; J6.19 75.4,1.99 ; J6.19 73.83,3.57 ; J1.A17 13.04,27.42 ; J1.A17 11.62,26 ; J1.A17 11.62,27.42 ; 13.53,27.27 J1.A18 ; J1.A18 13.53,28.69 ; J1.A18 14.95,27.27 ; J1.A18 14.95,28.69 ; J1.A19 13.04,29.96 ; J1.A19 11.62,28.54 ; J1.A19 13.04,28.54 ; J1.A19 11.62,29.96 ; 14.95,24.73 J1.A16 13.53,24.73 ; 57.37,70.45 J8.8 ; J8.8 57.37,68.87 ; J8.8 58.94,70.45 ; J8.8 58.94,68.87 ; 83.99,6.11 J6.12 ; J6.12 85.56,4.53 ; J6.12 85.56,6.11 ; J6.12 83.99,4.53 ; 13.53,29.81 J1.A20 ; J1.A20 14.95,31.23 ; J1.A20 14.95,29.81 ; J1.A20 13.53,31.23
  L05_DGND w0.381: 57.37,68.87 J8.8 ; J8.8 57.37,70.45 ; J8.8 58.94,70.45 ; J8.8 58.94,68.87
  BOTTOM w0.381: J8.8 58.94,70.45 ; J8.8 57.37,68.87 ; J8.8 58.94,68.87 ; J8.8 57.37,70.45
  BOTTOM w0.508: v1(73.34,70.33) 73.7,70.33 74.14,70.77 J2.13 ; v1(48.03,4.7) 47.28,3.95 J13.13
  vias: v1(1.31,72.38) v1(1.31,67.3) v1(1.31,62.22) v1(1.31,57.14) v1(1.31,52.06) v1(1.31,46.98) v1(1.31,41.9) v1(1.31,36.82) v1(1.31,31.74) v1(1.31,26.66) v1(1.31,21.58) v1(1.31,16.5) v1(1.31,11.42) v1(1.31,6.34) v1(2.96,1.51) v1(5.5,73.39) v1(5.5,70.85) v1(5.5,68.31) v1(5.5,65.77) v1(6.14,43.8) v1(6.14,41.26) v1(8.04,73.39) v1(8.04,70.85) v1(8.04,1.51) v1(12.87,73.39) v1(12.87,70.85) v1(13.12,1.51) v1(15.41,73.39) v1(15.41,70.85) v1(15.98,68.58) v1(16.87,62.41) v1(17.83,68.53) v1(18.39,50.29) v1(18.59,61.7) v1(19.94,36.2) v1(19.94,19.81) v1(21.72,55.24) v1(22.35,6.86) v1(25.53,57.02) v1(26.46,65.26) v1(29,65.26) v1(29.38,4.81) v1(34.46,4.81) v1(52.63,65.25) v1(52.63,63.98) v1(52.76,28.78) v1(58.21,7.1) v1(60.93,63.83) v1(63.27,64.9) v1(63.27,63.88) v1(83.35,1.26) v1(83.57,50.95) v1(84.24,57.64) v1(84.24,55.1) v1(86.08,48.95) v1(86.78,57.64) v1(86.78,55.1) v1(87.42,70.22) v1(87.42,67.68) v1(87.42,65.14) v1(88.43,1.26) v1(89.32,57.64) v1(89.32,55.1) v1(89.7,9.26) v1(89.96,70.22) v1(89.96,67.68) v1(89.96,65.14) v1(92.24,9.26) v1(92.5,65.14) v1(93.51,1.26) v1(94.78,37.71) v1(94.78,9.26) v1(95.04,65.14) v1(97.58,65.14) v1(98.08,12.05) v1(98.59,1.26) v1(100.12,67.68) v1(100.12,65.14) v1(103.67,56.5) v1(103.67,51.42) v1(103.67,46.34) v1(103.67,41.26) v1(103.67,36.18) v1(103.67,31.1) v1(103.67,26.02) v1(103.67,20.94) v1(103.67,15.86) v1(103.67,10.78) v1(103.76,67.68) v1(103.76,65.14)
GND: length 168.2
  TOP w0.305: J12.C10 v1(54.63,55.87)
  TOP w0.381: v1(39.69,38.34) 39.69,38.69 39.32,39.07 R13.2 ; R6.1 66.25,37.45 ; 39.32,34.91 R15.2 ; R15.2 38.65,35.42 ; R15.2 39.32,35.93 ; R9.2 55.19,38.74 v1(55.62,38.31) ; R11.2 55.19,35.93 ; R11.2 55.19,34.91 ; R11.2 54.52,35.42 ; v1(70.09,38.78) 69.8,39.07 R5.2 ; 69.8,34.91 R7.2 ; R7.2 69.8,35.93 ; R7.2 69.13,35.42 ; R10.1 52.86,36.59 ; R14.1 36.45,38.15
  TOP w0.508: J10.C3 v1(36.85,28.12) ; J10.C2 v1(34.31,27.93) ; J10.B10 v1(54.63,29.24) ; J10.C17 72.41,26.79 v1(70.97,28.23) ; J13.14 47.28,4.3 47.24,4.34 47.24,4.36 46.95,4.65 v1(46.95,5.22) ; J12.C11 v1(57.17,55.87) ; J9.C18 v1(74.95,45.71) ; J10.C1 v1(31.77,27.93) ; J2.14 74.14,70.6 75.2,69.54 75.2,69.48 75.67,69 75.93,69 v1(76.49,68.44) v1(76.49,65.9) ; J9.C2 v1(34.31,45.71) ; J11.B10 v1(54.63,19.03) ; J11.C10 v1(54.63,17.77) ; J10.B18 v1(74.95,29.19) ; J9.B2 v1(34.31,46.97) ; J11.B19 v1(77.49,19.03) ; J9.B18 v1(74.95,46.97) ; J10.C10 v1(54.63,28.05) ; J9.B19 v1(77.49,46.97) ; J11.B20 v1(80.03,19.03) ; J10.C18 v1(74.95,28.24) ; J9.C10 v1(54.63,45.71) ; J9.B10 v1(54.63,46.97) ; J11.C19 v1(77.49,17.77) ; J10.C19 v1(77.49,27.93)
  LO4_SIG2 w0.381: 98.88,55.77 J4.A1 ; J4.A1 100.44,57.33 ; J4.A1 100.44,55.77 ; J4.A1 98.88,57.33 ; J6.4 95.72,4.53 ; J6.4 94.15,6.11 ; J6.4 95.72,6.11 ; J6.4 94.15,4.53 ; 13.53,17.11 J1.A10 ; J1.A10 13.53,18.53 ; J1.A10 14.95,18.53 ; J1.A10 14.95,17.11 ; J7.2 71.59,4.53 ; J7.2 71.59,6.11 ; J7.2 70.02,4.53 ; J7.2 70.02,6.11 ; J1.A5 13.04,12.18 ; J1.A5 11.62,10.76 ; J1.A5 11.62,12.18 ; J1.A5 13.04,10.76 ; 96.69,6.11 J6.2 ; J6.2 98.26,4.53 ; J6.2 96.69,4.53 ; J6.2 98.26,6.11 ; 13.04,57.9 J1.A41 11.62,57.9
  L05_DGND w0.381: 98.88,55.77 J4.A1 ; J4.A1 100.44,57.33 ; J4.A1 98.88,57.33 ; J4.A1 100.44,55.77 ; J6.4 95.72,4.53 ; J6.4 94.15,6.11 ; J6.4 94.15,4.53 ; J6.4 95.72,6.11 ; 25.64,70.45 J5.4 ; J5.4 27.22,68.87 ; J5.4 25.64,68.87 ; J5.4 27.22,70.45 ; J8.2 51.32,70.45 ; J8.2 49.75,70.45 ; J8.2 51.32,68.87 ; J8.2 49.75,68.87 ; J1.A21 13.04,32.5 ; J1.A21 11.62,31.08 ; J1.A21 13.04,31.08 ; J1.A21 11.62,32.5 ; J5.2 24.68,68.87 ; J5.2 24.68,70.45 ; J5.2 23.1,68.87 ; J5.2 23.1,70.45 ; J7.2 71.59,4.53 ; J7.2 70.02,6.11 ; J7.2 71.59,6.11 ; J7.2 70.02,4.53 ; 96.69,6.11 J6.2 ; J6.2 96.69,4.53 ; J6.2 98.26,4.53 ; J6.2 98.26,6.11 ; J1.A41 13.04,56.48 ; J1.A41 11.62,57.9 ; J1.A41 13.04,57.9 ; J1.A41 11.62,56.48 ; J1.A10 14.95,18.53 ; J1.A10 13.53,18.53 ; J1.A10 13.53,17.11 ; J1.A10 14.95,17.11 ; J1.A5 13.04,12.18 ; J1.A5 11.62,12.18 ; J1.A5 13.04,10.76 ; J1.A5 11.62,10.76
  BOTTOM w0.381: J5.2 24.68,70.45 ; J5.2 23.1,68.87 ; J5.2 24.68,68.87 ; J5.2 23.1,70.45 ; 11.62,57.9 J1.A41 ; J1.A41 13.04,57.9 ; J1.A41 13.04,56.48 ; J1.A41 11.62,56.48 ; 98.63,55.52 J4.A1 ; J4.A1 98.63,57.58 ; J4.A1 100.69,55.52 ; J4.A1 100.69,57.58 ; 25.64,70.45 J5.4 ; J5.4 27.22,68.87 ; J5.4 27.22,70.45 ; J5.4 25.64,68.87 ; 95.72,4.53 J6.4 94.15,4.53 ; J6.2 98.26,4.53
  vias: v1(4.06,9.78) v1(4.06,7.24) v1(4.06,4.7) v1(5.71,8.51) v1(5.71,5.97) v1(5.71,3.43) v1(7.75,4.32) v1(15.49,3.17) v1(15.8,49.96) v1(22.01,56.63) v1(22.05,41.15) v1(26.96,56.63) v1(28.32,38.23) v1(28.32,35.18) v1(32.51,8.51) v1(33.91,7.11) v1(36.11,38.85) v1(37.25,36.1) v1(38,55.65) v1(40.72,19.02) v1(52.07,45.97) v1(52.24,38.34) v1(52.24,36.56) v1(58.42,1.14) v1(60.96,10.67) v1(65.91,38.56) v1(67.73,36.04) v1(70.92,55.98) v1(72.67,2.67) v1(74.93,40.01) v1(79.54,68.44) v1(79.54,65.9) v1(80.01,29.08) v1(80.95,1.26) v1(81.19,61.33) v1(81.32,22.08) v1(84.84,33.91) v1(87.42,61.99) v1(89.96,61.99) v1(90.17,48.51) v1(90.68,23.37) v1(90.68,21.08) v1(92.33,51.56) v1(92.5,61.99) v1(92.96,48.26) v1(94.87,53.98) v1(95.04,61.99) v1(97.58,61.99) v1(99.69,11.18) v1(99.69,8.64)
VCC1_3.3V: length 19.9
  TOP w0.508: J12.B11 v1(57.17,57.13)
  LO4_SIG2 w0.381: 52.29,70.45 J8.4 ; J8.4 53.86,68.87 ; J8.4 53.86,70.45 ; J8.4 52.29,68.87
  BOTTOM w0.381: J8.4 53.86,68.87 ; J8.4 52.29,68.87 ; J8.4 53.86,70.45 ; J8.4 52.29,70.45 ; 30.72,68.87 J5.8 ; J5.8 30.72,70.45 ; J5.8 32.3,68.87 ; J5.8 32.3,70.45 ; 28.18,70.45 J5.6 ; J5.6 29.76,70.45 ; J5.6 29.76,68.87 ; J5.6 28.18,68.87
VCC1_5V: length 12.3
  TOP w0.254: 68.74,38.05 Q6.1 69.3,38.43
  TOP w0.381: R1.1 72.81,38.83 ; R1.1 73.54,38.15 ; R1.1 72.08,38.15 ; 76.2,37.4 Q5.D ; Q5.D 76.93,36.77 ; Q5.D 76.93,38.03 ; Q5.D 77.66,37.4
  TOP w0.508: J9.B20 v1(80.03,46.97)
  L03_SIG1 w0.381: 96.34,57.33 J4.B1 ; J4.B1 97.9,57.33 ; J4.B1 96.34,55.77 ; J4.B1 97.9,55.77
  vias: v1(76.37,38.85) v1(77.64,38.85)
VCC1_15V: length 11
  TOP w0.381: 29.63,39.25 D1.A ; D1.A 31.49,39.25 ; D1.A 30.56,37.97 ; D1.A 30.56,40.54
  TOP w0.508: J12.B10 v1(54.63,57.13)
  LO4_SIG2 w0.381: J5.20 47.54,68.87 ; J5.20 47.54,70.45 ; J5.20 45.96,68.87 ; J5.20 45.96,70.45
  vias: v1(32.04,38.21) v1(33.67,38.21) v1(53.13,56.96)
VCC2_3.3V: length 17.9
  TOP w0.508: J11.C20 80.03,13.46 79.39,12.83 v1(79.39,11.59)
  L03_SIG1 w0.381: J6.6 93.18,6.11 ; J6.6 91.61,6.11 ; J6.6 91.61,4.53 ; J6.6 93.18,4.53 ; 89.07,6.11 J6.8 ; J6.8 90.64,6.11 ; J6.8 89.07,4.53 ; J6.8 90.64,4.53
  BOTTOM w0.381: 69.05,4.53 J7.4 69.05,6.11
  BOTTOM w0.508: 67.65,6.35 67.65,5.93 J7.4 67.65,4.71 67.65,4.45
  vias: v1(80.76,11.59)
VCC2_5V: length 14.9
  TOP w0.254: 54.13,38.05 Q8.1 54.7,38.43
  TOP w0.381: R8.1 58.94,38.15 ; R8.1 57.48,38.15 ; R8.1 58.21,38.83 ; 62.33,36.77 Q7.D ; Q7.D 63.06,37.4 ; Q7.D 62.33,38.03
  TOP w0.508: J9.C20 80.03,45.53 79.29,46.26 v1(78.78,46.26) ; J2.15 74.94,70.88 v1(76.01,69.81)
  BOTTOM w0.508: J2.15 74.94,70.88 v1(76.01,69.81)
  vias: v1(63.79,38.47) v1(63.79,36.94)
VCC2_15V: length 14.3
  TOP w0.381: D2.A 30.56,36.98 ; D2.A 30.56,34.42 ; D2.A 29.63,35.7 ; D2.A 31.49,35.7 ; J10.B2 35.17,31.29 ; J10.B2 33.44,31.29 ; J10.B2 34.31,29.47 ; J10.B2 34.31,33.11
  LO4_SIG2 w0.381: J6.20 75.4,6.11 ; J6.20 73.83,6.11 ; J6.20 75.4,4.53 ; J6.20 73.83,4.53
  vias: v1(16.04,28.18) v1(17.82,30.59) v1(32.17,35.67) v1(33.8,35.67)
VCC3_5V: length 51.7
  TOP w0.254: 38.82,38.43 Q10.1 38.26,38.05
  TOP w0.381: 45.72,37.4 Q9.D ; Q9.D 46.45,36.77 ; Q9.D 46.45,38.03 ; Q9.D 47.18,37.4 ; 41.6,38.15 R12.1 ; R12.1 42.33,38.83 ; R12.1 43.06,38.15
  TOP w0.508: J13.15 46.48,4.04 v1(45.66,4.86) 44.69,5.83 32.27,5.83 29,9.1 29,27.04 v1(27.73,28.31) ; J10.B3 v1(36.85,29.27)
  BOTTOM w0.508: J13.15 46.48,4.04 v1(45.66,4.86)
  vias: v1(47.92,38.34) v1(47.92,36.94)
M5CONN_J4_A8PIN: length 94.6
  TOP w0.203: v1(24.92,13.56) 24.92,12.62 R34.1
  L03_SIG1 w0.203: J4.A8 98.39,37.5 96.1,37.5 95.07,36.47 95.07,33.58 82.75,21.26 56.9,21.26 55.47,19.84 55.47,16.71 53.92,15.16 45.95,15.16 44.68,16.43 31.62,16.43 29.44,18.62 26.37,18.62 25.86,18.11 25.86,16.18 24.92,15.24 v1(24.92,13.56)
P1_2_CTRAP_1: length 90.6
  TOP w0.152: J10.C12 v1(59.71,28.3)
  LO4_SIG2 w0.152: v1(59.71,28.3) 60.99,28.3 64.69,24.59 93.52,24.59 J4.B15
  BOTTOM w0.152: v1(59.71,28.3) 58.08,26.67 20.7,26.67 16.93,22.9 J1.A14
P1_3_CTRAP_2: length 145.4
  TOP w0.152: J11.B14 v1(64.79,19.08)
  LO4_SIG2 w0.152: J1.A25 12.56,37.09 18.04,37.09 30.64,24.49 59.37,24.49 v1(64.79,19.08) 66.79,17.08 80.13,17.08 83.11,20.07 91.31,20.07 92.08,20.83 93.75,20.83 v1(94.53,20.05)
  BOTTOM w0.152: v1(94.53,20.05) 94.83,19.75 98.42,19.75 J4.A15 ; J13.41 36.08,7.76 36.83,8.51 36.83,11.18 38.91,13.26 38.91,13.27 43.09,17.45 43.09,19.98 45.2,22.08 63.16,22.08 64.79,20.46 v1(64.79,19.08)
P2_1_SCB7_SDA: length 39.3
  TOP w0.305: J11.C4 v1(39.39,17.77)
  BOTTOM w0.152: J1.B1 9.89,6.39 11.85,4.43 14.1,4.43 17.79,8.11 28.22,8.11 32.04,11.94 32.06,11.94 36.87,16.75 38.37,16.75 v1(39.39,17.77)
P2_2_SCB7_SCL: length 29.1
  TOP w0.305: J11.C2 v1(34.31,17.77)
  BOTTOM w0.152: v1(34.31,17.77) 34.31,17.23 27.59,10.52 18.64,10.52 14.51,6.39 J1.A1
P2_4_CTRAP_3: length 111
  TOP w0.152: J12.C4 v1(39.39,55.79)
  LO4_SIG2 w0.152: v1(39.39,55.79) 39.79,56.2 39.79,66.99 40.39,67.59 40.39,70.94 J5.13
  BOTTOM w0.152: J2.41 85.34,63.18 80.32,58.17 77.23,58.17 77.22,58.15 41.74,58.15 v1(39.39,55.79) 39.39,54.88 32.26,47.75 31.45,47.75 28.27,44.58 17.55,44.58 15.33,46.8 13.54,46.8 13.31,47.03 J1.A33
P3_0_SCB6_MISO: length 117.7
  TOP w0.152: v1(90.81,27.3) 90.81,27.99 91.65,28.83 R30.1
  TOP w0.305: J11.B3 v1(36.85,19.03)
  LO4_SIG2 w0.152: v1(36.85,19.03) 39.5,16.38 57.43,16.38 62,11.81 78.11,11.81 79.38,10.54 86.53,10.54 88.06,12.06 93.09,12.06 93.34,11.81 v1(95.63,11.81)
  BOTTOM w0.152: v1(36.85,19.03) 34.68,21.2 30.39,21.2 28.62,19.42 28.62,17.39 26.33,15.1 18.07,15.1 14.52,11.54 14.11,11.54 12.33,9.76 J1.A3 ; v1(95.63,11.81) 95.76,11.94 95.76,17.14 95.63,17.28 95.63,17.29 93.16,19.75 93.16,20.5 91.88,21.79 91.88,26.23 v1(90.81,27.3)
P3_1_SCB6_MOSI: length 119.8
  TOP w0.152: v1(90.55,11.3) 90.55,16.76 88.52,18.8 88.52,29.34 91.31,32.13 91.31,32.89 92.51,34.09 R25.1
  TOP w0.305: J11.C3 v1(36.85,17.77)
  LO4_SIG2 w0.152: v1(90.55,11.3) 89.28,11.3 86.94,8.97 62.66,8.97 61.93,9.7 61.93,11.24 57.24,15.93 38.69,15.93 v1(36.85,17.77)
  BOTTOM w0.152: J1.B2 10.43,6.63 11.74,5.32 14.21,5.32 17.73,8.84 27.92,8.84 v1(36.85,17.77)
P3_2_SCB6_CLK: length 111.9
  TOP w0.152: R32.1 92.52,23.56 91.57,22.61 91.57,20.13 92.65,19.05 94.74,19.05 96.39,17.4 v1(96.39,10.54)
  TOP w0.305: J11.C1 v1(31.77,17.77)
  LO4_SIG2 w0.152: v1(31.77,17.77) 34.07,15.47 57.05,15.47 60.33,12.19 60.33,10.16 61.98,8.51 92.46,8.51 94.49,10.54 v1(96.39,10.54)
  BOTTOM w0.152: v1(31.77,17.77) 31.77,16.22 26.85,11.3 18.29,11.3 14.64,7.66 J1.A2
P3_3_SCB6_SEL0: length 115.6
  TOP w0.152: R31.1 v1(91.24,25.32)
  TOP w0.305: J11.B4 v1(39.39,19.03)
  LO4_SIG2 w0.152: v1(39.39,19.03) 40.39,18.03 40.39,17.5 41.05,16.84 57.62,16.84 62.09,12.37 85.43,12.37 86.02,12.95 94.36,12.95 v1(94.74,12.57)
  BOTTOM w0.152: v1(91.24,25.32) 91.31,25.25 91.31,21.72 91.42,21.61 91.42,21.6 91.88,21.14 91.88,19.88 92.26,19.5 92.64,19.5 94.75,17.39 94.79,17.39 95.17,17.02 95.17,13 v1(94.74,12.57) ; J1.B3 8.52,9.87 10.2,11.54 10.94,11.54 12.21,12.81 12.74,12.81 13.88,13.96 15.94,13.96 17.96,15.98 25.02,15.98 25.88,16.84 25.88,17.75 30.1,21.97 36.45,21.97 v1(39.39,19.03)
P3_4_SCB6_SEL1: length 28.1
  TOP w0.305: J11.B2 v1(34.31,19.03)
  BOTTOM w0.152: v1(34.31,19.03) 33.07,20.27 33.07,20.32 30.91,20.32 29.63,19.04 29.63,17 26.83,14.2 19.4,14.2 18.67,13.46 17.91,13.46 14.64,10.2 J1.A4
P3_5_SCB6_SEL2: length 30.8
  TOP w0.305: J11.B1 v1(31.77,19.03)
  BOTTOM w0.152: v1(31.77,19.03) 31.1,19.03 30.65,18.58 30.65,16.62 26.67,12.65 19.76,12.65 19.18,12.06 17.98,12.06 14.79,8.88 13.88,8.88 12.74,7.73 11.98,7.73 10.43,9.28 J1.B4
P4_4_ENPOW1: length 98.7
  TOP w0.152: J10.B12 v1(59.71,29.21)
  LO4_SIG2 w0.152: v1(59.71,29.21) 59.11,29.21 58.84,28.95 58.84,27.95 59.21,27.58 60.56,27.58 64.01,24.13 92.46,24.13 95.54,21.04 95.54,20.03 J4.B16
  BOTTOM w0.152: J1.B14 12.77,22.9 13.81,23.94 17.08,23.94 20.29,27.15 57.65,27.15 v1(59.71,29.21)
P5_0_U4_H: length 129
  TOP w0.152: J9.B15 v1(67.33,46.97)
  LO4_SIG2 w0.152: v1(67.33,46.97) 61.72,41.36 25.17,41.36 17.1,49.43 17.1,50.46 15.23,52.34 13.81,52.34 12.77,53.38 J1.B38
  BOTTOM w0.152: J6.1 97.48,2.86 98.78,4.17 98.78,6.25 80.9,24.13 80.9,38.86 76.45,43.31 69.09,43.31 68.2,44.2 68.2,46.1 v1(67.33,46.97)
P5_1_U4_L: length 121.3
  TOP w0.152: J9.C14 v1(64.79,45.63)
  LO4_SIG2 w0.152: v1(64.79,45.63) 60.94,41.78 25.66,41.78 17.41,50.04 17.41,51.17 15.2,53.38 J1.A38
  BOTTOM w0.152: J6.3 94.94,2.86 96.27,4.19 96.27,6.6 94.11,8.76 94.11,10.49 79.38,25.22 79.38,39.88 76.33,42.93 67.49,42.93 v1(64.79,45.63)
P6_0_U1_H: length 99.8
  TOP w0.152: J10.C15 v1(67.33,27.91)
  LO4_SIG2 w0.152: J4.B10 96.56,33.69 93.22,30.35 90.3,30.35 87.54,27.6 78.72,27.6 77.75,28.56 77.22,28.56 76.25,27.6 68.44,27.6 68.12,27.91 v1(67.33,27.91)
  BOTTOM w0.152: v1(67.33,27.91) 62.93,23.52 22.25,23.52 15.42,16.69 13.82,16.69 12.65,17.86 11.99,17.86 10.76,19.09 J1.B11
P6_1_U1_L: length 94
  TOP w0.152: J10.B15 v1(67.33,29.27)
  LO4_SIG2 w0.152: J4.B9 92.13,31.24 69.3,31.24 v1(67.33,29.27)
  BOTTOM w0.152: J1.A11 13.55,19.09 13.72,18.92 16.89,18.92 22.1,24.13 62.18,24.13 67.32,29.27 v1(67.33,29.27)
P6_2_V1_H: length 94
  TOP w0.152: J10.C14 v1(64.79,27.85)
  LO4_SIG2 w0.152: J4.B12 90.33,28.61 88.4,26.68 65.96,26.68 v1(64.79,27.85)
  BOTTOM w0.152: v1(64.79,27.85) 61.6,24.66 21.87,24.66 16.52,19.32 13.81,19.32 13,20.13 11.42,20.13 11.19,20.36 J1.B12
P6_3_V1_L: length 91.2
  TOP w0.152: J10.B14 v1(64.79,29.27)
  LO4_SIG2 w0.152: J4.B11 95.43,29.46 90.3,29.46 87.97,27.14 66.92,27.14 v1(64.79,29.27)
  BOTTOM w0.152: v1(64.79,29.27) 60.71,25.2 21.63,25.2 16.73,20.29 14.3,20.29 J1.A12
P6_4_W1_H: length 96.1
  TOP w0.152: J10.C13 62.25,27.87 v1(62.25,28.01)
  LO4_SIG2 w0.152: J4.B14 94.62,26.04 64.22,26.04 v1(62.25,28.01)
  BOTTOM w0.152: v1(62.25,28.01) 59.97,25.73 21.29,25.73 16.95,21.4 13.65,21.4 12.84,20.59 11.72,20.59 10.68,21.63 J1.B13
P6_5_W1_L: length 91.9
  TOP w0.152: J10.B13 v1(62.25,29.27)
  LO4_SIG2 w0.152: v1(62.25,29.27) 65.14,26.38 91.78,26.38 92.46,27.05 96.14,27.05 J4.B13
  BOTTOM w0.152: v1(62.25,29.27) 59.19,26.21 21.01,26.21 16.64,21.84 13.49,21.84 13.27,21.63 J1.A13
P7_0_U2_H: length 145.9
  TOP w0.152: J11.B11 v1(57.17,19.11)
  LO4_SIG2 w0.152: J1.B22 12.64,33.06 13.94,31.76 14.8,31.76 15.28,32.24 17.95,32.24 29.47,20.73 55.55,20.73 v1(57.17,19.11) 57.17,19.02 v1(62.56,13.62) 63.16,13.62 63.3,13.49 84.35,13.49 85.22,14.35 94.8,14.35 98.42,17.97 98.42,18.97 99.14,19.7 100.85,19.7 101.39,20.23 101.39,31.96 J4.A10
  BOTTOM w0.152: J13.17 45.68,3.94 44.32,5.3 44.32,8 45.59,9.27 48.9,9.27 51.93,12.31 61.24,12.31 v1(62.56,13.62)
P7_1_U2_L: length 146.1
  TOP w0.152: J11.C12 v1(59.71,17.95)
  LO4_SIG2 w0.152: J1.A22 18.02,33.06 29.84,21.24 56.41,21.24 v1(59.71,17.95) 63.56,14.1 82.93,14.1 83.82,14.99 91.75,14.99 v1(92.75,15.99)
  BOTTOM w0.152: v1(59.71,17.95) 59.71,15.51 57.91,13.72 47.16,13.72 44.55,11.11 44.55,9.12 43.94,8.51 43.94,4.98 44.88,4.04 J13.19 ; J4.A9 98.35,34.92 97.65,34.92 97.64,34.94 94.25,34.94 89.92,30.61 89.92,18.82 v1(92.75,15.99)
P7_2_V2_H: length 149.4
  TOP w0.152: v1(92.75,17.51) 91.23,17.51 89.53,19.2 89.53,27.6 R27.1 ; J11.C13 v1(62.25,17.95)
  LO4_SIG2 w0.152: v1(92.75,17.51) 83.61,17.51 81.32,15.23 64.97,15.23 v1(62.25,17.95) 57.96,22.23 30.63,22.23 18.3,34.56 13.68,34.56 12.87,35.37 11.8,35.37 10.76,34.33 J1.B23
  BOTTOM w0.152: v1(62.25,17.95) 61.76,17.95 59.87,19.84 59.21,19.84 58.67,19.3 58.67,16.89 56.64,14.86 43.94,14.86 41.02,11.94 41.02,5.97 40.08,5.03 J13.31
P7_2_V2_H/MISO: length 8.2
  TOP w0.152: R30.2 R27.2 95.27,30.59 96,29.86 98.42,29.86 J4.A12
P7_3_V2_L: length 146.6
  TOP w0.152: R26.1 89.03,28.84 89.03,18.97 91.25,16.75 v1(94.53,16.75) ; J11.B12 v1(59.71,19.11)
  LO4_SIG2 w0.152: J1.A23 13.48,34.33 13.55,34.25 14.9,34.25 15.37,33.78 18.16,33.78 30.1,21.84 56.97,21.84 v1(59.71,19.11) 64.34,14.48 81.66,14.48 82.68,15.49 91.06,15.49 92.32,16.75 v1(94.53,16.75)
  BOTTOM w0.152: J13.29 40.88,4.3 41.53,4.95 41.53,11.43 44.45,14.35 57.15,14.35 59.05,16.26 59.05,18.46 v1(59.71,19.11)
P7_3_V2_L/MOSI: length 7.9
  TOP w0.152: R25.2 R26.2 94.08,32.4 98.42,32.4 J4.A11
P7_4_W2_H: length 136.7
  TOP w0.152: J11.C14 v1(64.79,17.95) ; R29.1 v1(92.52,20.14)
  LO4_SIG2 w0.152: J1.B24 11.31,35.6 11.54,35.82 12.86,35.82 13.68,36.64 17.75,36.64 30.93,23.45 59.28,23.45 v1(64.79,17.95) 66.24,16.5 80.56,16.5 83.39,19.33 91.66,19.33 92.47,20.14 v1(92.52,20.14)
  BOTTOM w0.152: J13.33 39.28,5.5 40.39,6.61 40.39,12.32 43.43,15.37 56.26,15.37 58.29,17.4 58.29,19.56 59.05,20.32 60.12,20.32 61.93,18.52 64.22,18.52 v1(64.79,17.95)
P7_4_W2_H/CLK: length 8.4
  TOP w0.152: J4.A14 98.42,24.78 95.26,24.78 94.05,23.57 R32.2 R29.2
P7_5_W2_L: length 137.1
  TOP w0.152: R28.1 91.55,27.08 90.04,25.57 90.04,19.47 v1(91.01,18.5) ; J11.B13 v1(62.25,19.11)
  LO4_SIG2 w0.152: J1.A24 18.12,35.6 30.73,22.99 58.37,22.99 v1(62.25,19.11) 65.48,15.88 80.98,15.88 83.6,18.5 v1(91.01,18.5)
  BOTTOM w0.152: J13.35 38.48,5.58 39.88,6.99 39.88,12.57 43.31,16 56.13,16 57.91,17.79 57.91,19.81 58.93,20.83 60.53,20.83 v1(62.25,19.11)
P7_5_W2_L/SEL0: length 8.1
  TOP w0.152: R31.2 R28.2 94.02,27.16 94.18,27.32 98.42,27.32 J4.A13
P8_0_ENPOW2: length 142.6
  TOP w0.152: v1(57.17,17.95) J11.C11
  LO4_SIG2 w0.152: J4.A16 94.8,13.59 85.47,13.59 84.71,12.83 62.29,12.83 v1(57.17,17.95) 54.84,20.27 29.13,20.27 18.05,31.36 16.93,31.36 14.79,29.21 14,29.21 12.68,30.53 11.96,30.53 10.67,31.83 10.06,31.83 8.86,33.02 8.03,33.02 7.28,33.77 7.28,35.62 J1.B25
  BOTTOM w0.152: J13.39 36.88,7.14 39.37,9.63 39.37,13.08 43.04,16.75 55.97,16.75 v1(57.17,17.95)
P8_1_VBEMF_U/IU(2): length 145.6
  TOP w0.203: J1.B17 10.75,26.71 12.02,25.44 12.65,25.44 13.85,24.24 17.9,24.24 v1(24.55,17.59) ; v1(47.01,17.77) J11.C7 47.01,13.6 47.67,12.94 54.58,12.94 55.35,12.18 64.86,12.18 J14.2
  L03_SIG1 w0.203: v1(24.55,17.59) 23.13,19.01 23.13,21.43 24.56,22.86 44.51,22.86 48.01,19.36 48.01,18.77 v1(47.01,17.77) 47.12,17.65 48.27,17.65 48.89,18.27 48.89,19.48 49.27,19.87 50.73,19.87 56.01,25.15 83.44,25.15 91.82,33.53 91.82,41.47 96.74,46.39 J4.B5
P8_1_VBEMF_U/IU(2)_L: length 18.5
  BOTTOM w0.203: J13.1 52.08,3.67 52.19,3.78 52.19,7.94 53.1,8.85 62.35,8.85 J14.1
P8_1_VBEMF_U/IU(2)_R: length 23.1
  TOP w0.203: J13.2 52.08,4.02 52.24,4.18 52.24,7.2 53.08,8.04 66.61,8.04 J14.3
P8_2_VBEMF_U/IU(3)/PFC_I_PHASE_IN_A: length 77.7
  TOP w0.203: J1.B28 12.64,40.68 13.71,39.61 18.9,39.61 20.27,40.98 20.27,42.95 26.7,49.37 26.7,54.71 25.76,55.65 25.18,55.65 v1(24.84,55.99) ; J18.2 34.05,66.36 J5.10 34.92,69.66 35.12,69.46 35.12,67.81 36.41,66.52 38.57,66.52 39.73,65.36 39.73,62.92 40.53,62.12 40.53,56.65 40.97,56.21 41.51,56.21 41.6,56.12 41.6,56.12 v1(41.93,55.79) J12.C5
  L03_SIG1 w0.203: v1(41.93,55.79) 42.37,56.24 42.75,56.24 42.98,56.01 42.98,55.09 42.77,54.89 26.48,54.89 25.72,55.65 25.18,55.65 v1(24.84,55.99)
P8_2_VBEMF_U/IU(3)/PFC_I_PHASE_IN_A_L: length 41.8
  L03_SIG1 w0.203: v1(51.18,66.46) 35.27,66.46 J18.1
  BOTTOM w0.203: v1(51.18,66.46) 63.31,66.46 63.83,66.98 63.86,66.98 63.92,67.04 68.04,67.04 69.25,68.26 69.25,70.85 69.34,70.94 J2.1
P8_2_VBEMF_U/IU(3)/PFC_I_PHASE_IN_A_N: length 67.6
  TOP w0.203: J12.B5 v1(41.93,57.07) 41.47,56.62 41.14,56.62 40.93,56.82 40.93,62.29 40.13,63.09 40.13,65.53 38.73,66.93 36.58,66.93 35.52,67.98 35.52,69.46 35.73,69.66 J5.12 ; v1(24.84,54.9) 25.18,55.24 25.59,55.24 26.29,54.54 26.29,49.54 19.86,43.11 19.86,41.14 18.74,40.02 16.88,40.02 16.59,40.3 R19.1 15.62,40.77 15.53,40.68 J1.A28
  L03_SIG1 w0.203: v1(41.93,57.07) 42.36,56.64 42.92,56.64 43.38,56.18 43.38,54.92 42.94,54.48 26.31,54.48 25.55,55.24 25.18,55.24 v1(24.84,54.9)
P8_2_VBEMF_U/IU(3)/PFC_I_PHASE_IN_A_R: length 50.3
  TOP w0.203: J2.2 69.34,69.5 73,65.84 73,65.81 73,64.95 v1(73.95,63.99)
  L03_SIG1 w0.203: J18.3 39.54,65.64 43.06,65.64 43.2,65.79 50.7,65.79 50.84,65.64 51.67,65.64 52.55,66.52 74.19,66.52 74.79,65.92 74.79,64.83 v1(73.95,63.99)
P8_3_IAVG_IDCLINK(2): length 76.3
  TOP w0.203: J17.2 36.18,10.65 37.83,12.31 42.33,12.31 43.22,13.19 43.22,17.79 v1(44.47,19.03) J11.B6 ; v1(26.04,20.83) 26.04,20.98 15.38,31.64 14.07,31.64 12.8,32.91 11.87,32.91 10.43,31.47 J1.B20 ; R34.2 23.42,12.61 v1(23.42,9.68)
  L03_SIG1 w0.203: v1(26.04,20.83) 42.67,20.83 v1(44.47,19.03)
  LO4_SIG2 w0.203: v1(23.42,9.68) 29.18,9.68 31.22,7.65 33.43,7.65 34.62,8.84 34.62,9.72 J17.2
P8_3_IAVG_IDCLINK(2)_L: length 20.9
  L03_SIG1 w0.203: v1(45.7,7.41) 36.25,7.41 J17.1
  BOTTOM w0.203: J13.9 48.88,4.11 48.69,4.3 48.69,5.31 48.05,5.96 47.16,5.96 v1(45.7,7.41)
P8_4_VDCLINK1: length 102.4
  TOP w0.203: v1(39.39,29.26) 39.39,29.27 J10.B4
  L03_SIG1 w0.203: J4.B4 90.68,42.49 90.68,40.69 83.65,33.66 41.78,33.66 39.93,31.8 39.93,29.81 39.39,29.28 v1(39.39,29.26) 37.3,31.36 22.34,31.36 17.53,26.54 13.76,26.54 12.65,25.44 J1.B16
P9_0_VBEMF_U/IU(4): length 118
  TOP w0.203: v1(84,40.58) 84.81,39.76 84.81,38.89 84.15,38.23 84.15,8.49 J6.10 ; J1.A42 16,58.46 23.93,50.52 v1(23.93,48.74) ; J9.B6 v1(44.47,46.97)
  L03_SIG1 w0.203: v1(23.93,48.74) 25.16,48.74 25.76,49.34 42.1,49.34 v1(44.47,46.97) 49.38,42.06 79.88,42.06 81.37,40.58 v1(84,40.58)
P9_1_PFC_V_PHASE_IN_A: length 198.1
  TOP w0.203: J4.A3 98.39,52.74 86.32,52.74 84.88,51.29 84.88,48.61 v1(85.27,48.22) 85.27,47.73 85.96,47.05 85.96,16.49 v1(86.3,16.15) ; J1.B45 10.74,62.27 11.85,63.38 12.77,63.38 13.68,62.47 15.09,62.47 16.83,60.74 17.29,60.74 v1(17.63,61.08) ; J8.9 62.25,70.65 62.25,67.96 63.72,66.48 70.52,66.48 71.78,65.22 71.78,63.55 70.43,62.2 69.5,62.2 68.8,61.5 68.8,59.49 69.05,59.23 J12.B16 69.87,57.21 v1(69.85,57.19)
  L03_SIG1 w0.203: v1(69.85,57.19) 68.91,57.19 ; 68.91,57.19 68.71,56.99 68.71,55.57 74.38,49.89 83.11,49.89 84.79,48.22 v1(85.27,48.22) ; 68.91,57.19 68.71,57.4 68.71,58.49 67.68,59.51 20.23,59.51 19,60.74 17.98,60.74 v1(17.63,61.08) ; J7.9 61.82,3.95 61.82,7.11 62.46,7.75 64.62,7.75 65.57,8.7 72.21,8.7 77.26,13.75 84.83,13.75 85.96,14.88 85.96,15.8 v1(86.3,16.15)
P9_1_PFC_V_PHASE_IN_A_N: length 169.8
  TOP w0.203: v1(84.5,47.45) 84.99,47.45 85.55,46.88 85.55,16.49 v1(85.21,16.15) ; R22.1 17.68,59.94 v1(17.63,59.99) 17.29,60.33 16.66,60.33 14.93,62.06 12.54,62.06 J1.A45 ; v1(67.34,57.21) 67.34,57.22 67.33,57.24 J12.B15 68.14,59.23 68.39,59.49 68.39,61.67 69.33,62.6 70.26,62.6 71.38,63.72 71.38,65.05 70.35,66.08 63.55,66.08 61.84,67.79 61.84,69.23 61.41,69.66 J8.10
  L03_SIG1 w0.203: v1(17.63,59.99) 17.98,60.33 18.83,60.33 20.06,59.1 67.52,59.1 68.3,58.32 68.3,57.41 68.1,57.21 ; v1(85.21,16.15) 85.55,15.8 85.55,15.05 84.66,14.15 77.1,14.15 72.05,9.1 65.4,9.1 64.45,8.16 62.29,8.16 61.41,7.28 61.41,6.08 J7.10 ; 68.1,57.21 68.3,57.01 68.3,55.4 74.21,49.49 82.95,49.49 84.5,47.93 v1(84.5,47.45) ; 68.1,57.21 v1(67.34,57.21)
P9_2_BRAKEGATE1: length 107.1
  TOP w0.152: J10.C11 v1(57.17,28.06)
  LO4_SIG2 w0.152: v1(57.17,28.06) 56.3,28.92 56.3,29.96 59.11,32.77 80.19,32.77 91.82,44.4 91.82,48.71 J4.B2
  BOTTOM w0.152: v1(57.17,28.06) 55.63,29.6 55.63,30.4 55.04,30.99 21.84,30.99 15.25,24.4 13.47,24.4 13.24,24.17 J1.A15
P9_3_BRAKETEMP1: length 105.9
  TOP w0.152: J10.B11 v1(57.17,29.27)
  LO4_SIG2 w0.152: v1(57.17,29.27) 59.9,32 80.14,32 92.37,44.24 92.37,46.72 J4.B3
  BOTTOM w0.152: J1.B15 10.76,24.17 12.01,25.43 12.67,25.43 13.97,26.72 16.69,26.72 21.58,31.61 55.82,31.61 57.17,30.26 v1(57.17,29.27)
P10_0_PFC_KIL_EXTRA1: length 177.6
  TOP w0.152: J11.C15 v1(67.33,17.77)
  LO4_SIG2 w0.152: v1(67.33,17.77) 59.8,25.3 31.96,25.3 19.64,37.62 14.76,37.62 J1.A26 ; v1(65.96,36.04) 71.5,41.58 71.5,46.48 67.69,50.29 57.86,50.29 57.82,50.33 57.58,50.33 48.73,59.18 43.94,59.18 43.85,59.27 43.84,59.27 40.48,62.63 40.48,62.65 40.25,62.87 40.25,66.1 42.93,68.78 42.93,70.36 43.56,70.99 54.41,70.99 J8.5
  BOTTOM w0.152: v1(65.96,36.04) 69.72,32.28 69.72,20.17 v1(67.33,17.77) 71.49,13.6 71.49,9.26 70.34,8.11 68.18,8.11 67.07,7 67.07,4.12 J7.5
P10_1_EXTRA2: length 67.8
  TOP w0.152: J11.B15 v1(67.33,19.03)
  LO4_SIG2 w0.152: J1.B26 12.68,38.14 13.72,39.18 14.96,39.18 16.06,38.07 19.83,38.07 31.83,26.07 60.06,26.07 66.21,19.93 66.43,19.93 v1(67.33,19.03)
P10_2_EXTRA3: length 68.8
  TOP w0.152: J11.C16 v1(69.87,17.77)
  LO4_SIG2 w0.152: v1(69.87,17.77) 66.95,20.69 66.16,20.69 60.31,26.54 32,26.54 20.02,38.53 16.25,38.53 15.15,39.63 12.56,39.63 J1.A27
P10_3_EXTRA4: length 74.5
  TOP w0.152: J11.B16 v1(69.87,19.03)
  LO4_SIG2 w0.152: v1(69.87,19.03) 67.58,21.32 66.17,21.32 60.47,27.03 33.57,27.03 32.03,28.56 30.66,28.56 20.24,38.99 16.69,38.99 15.75,39.93 15.75,40.89 14.75,41.9 13.88,41.9 12.74,40.75 12.11,40.75 10.76,39.41 J1.B27
P10_4_VBEMF_V/IV(4): length 121.4
  TOP w0.203: J1.B42 12.66,58.46 13.93,57.18 16.28,57.18 23.08,50.38 v1(23.08,47.92) ; J9.C6 v1(44.47,45.71) ; v1(83.99,39.22) 83.46,38.69 83.46,9.09 J6.16
  L03_SIG1 w0.203: v1(83.99,39.22) 81.33,39.22 79.4,41.15 49.03,41.15 v1(44.47,45.71) 41.45,48.73 26.12,48.73 25.3,47.9 23.1,47.9 v1(23.08,47.92)
P10_5_IAVG/IDCLINK(1): length 129.7
  TOP w0.203: R33.1 21.92,16.86 20.62,18.16 16.05,18.16 15.04,19.18 14.09,19.18 12.53,17.61 11.89,17.61 10.83,16.55 J1.B9 ; J10.C5 v1(41.93,28.2) ; J4.B8 90.52,38.77 v1(90.21,38.47)
  L03_SIG1 w0.203: v1(90.21,38.47) 90.21,38.27 84.84,32.89 42.67,32.89 40.77,30.99 40.77,29.2 41.77,28.2 v1(41.93,28.2) 42.08,28.2 42.27,28.39 42.56,28.39 42.79,28.16 42.79,27.74 42.31,27.27 20.34,27.27 15.95,22.88 15.95,21.16 15.85,21.06 15.85,19.66 15.48,19.29 13.64,19.29 12.78,20.15 11.89,20.15 11.27,19.53 11.27,18.65 11.56,18.36 11.56,17.44 10.63,16.51 8.56,16.51 J1.B9
P10_5_IAVG/IDCLINK(1)_N: length 43.5
  TOP w0.203: v1(16.48,20.87) 16.56,20.78 16.56,19.84 R18.1 ; v1(41.93,29.14) J10.B5
  L03_SIG1 w0.203: v1(41.93,29.14) 42.27,28.8 42.73,28.8 43.2,28.33 43.2,27.58 42.48,26.86 20.51,26.86 16.36,22.71 16.36,21.05 16.41,21 16.41,20.93 v1(16.48,20.87) 16.26,20.65 16.26,19.49 15.65,18.88 13.93,18.88 13.93,18.88 13.8,18.88 13.17,18.26 13.17,17.39 J1.A9
P10_6_VBEMF_V/IV(2): length 133.8
  TOP w0.203: J15.2 54.14,12.31 46.77,12.31 45.63,13.44 45.63,17.66 v1(47.01,19.03) J11.B7 ; v1(24.55,19.21) 17.11,26.66 13.97,26.66 12.65,27.98 J1.B18
  L03_SIG1 w0.203: v1(24.55,19.21) 23.74,20.03 23.74,21.18 24.81,22.25 43.97,22.25 v1(47.01,19.03) 46.14,18.17 46.14,17.34 46.52,16.96 50.23,16.96 51.18,17.91 51.18,19.3 56.01,24.13 83.44,24.13 92.62,33.31 92.62,39.61 96.87,43.85 J4.B6
